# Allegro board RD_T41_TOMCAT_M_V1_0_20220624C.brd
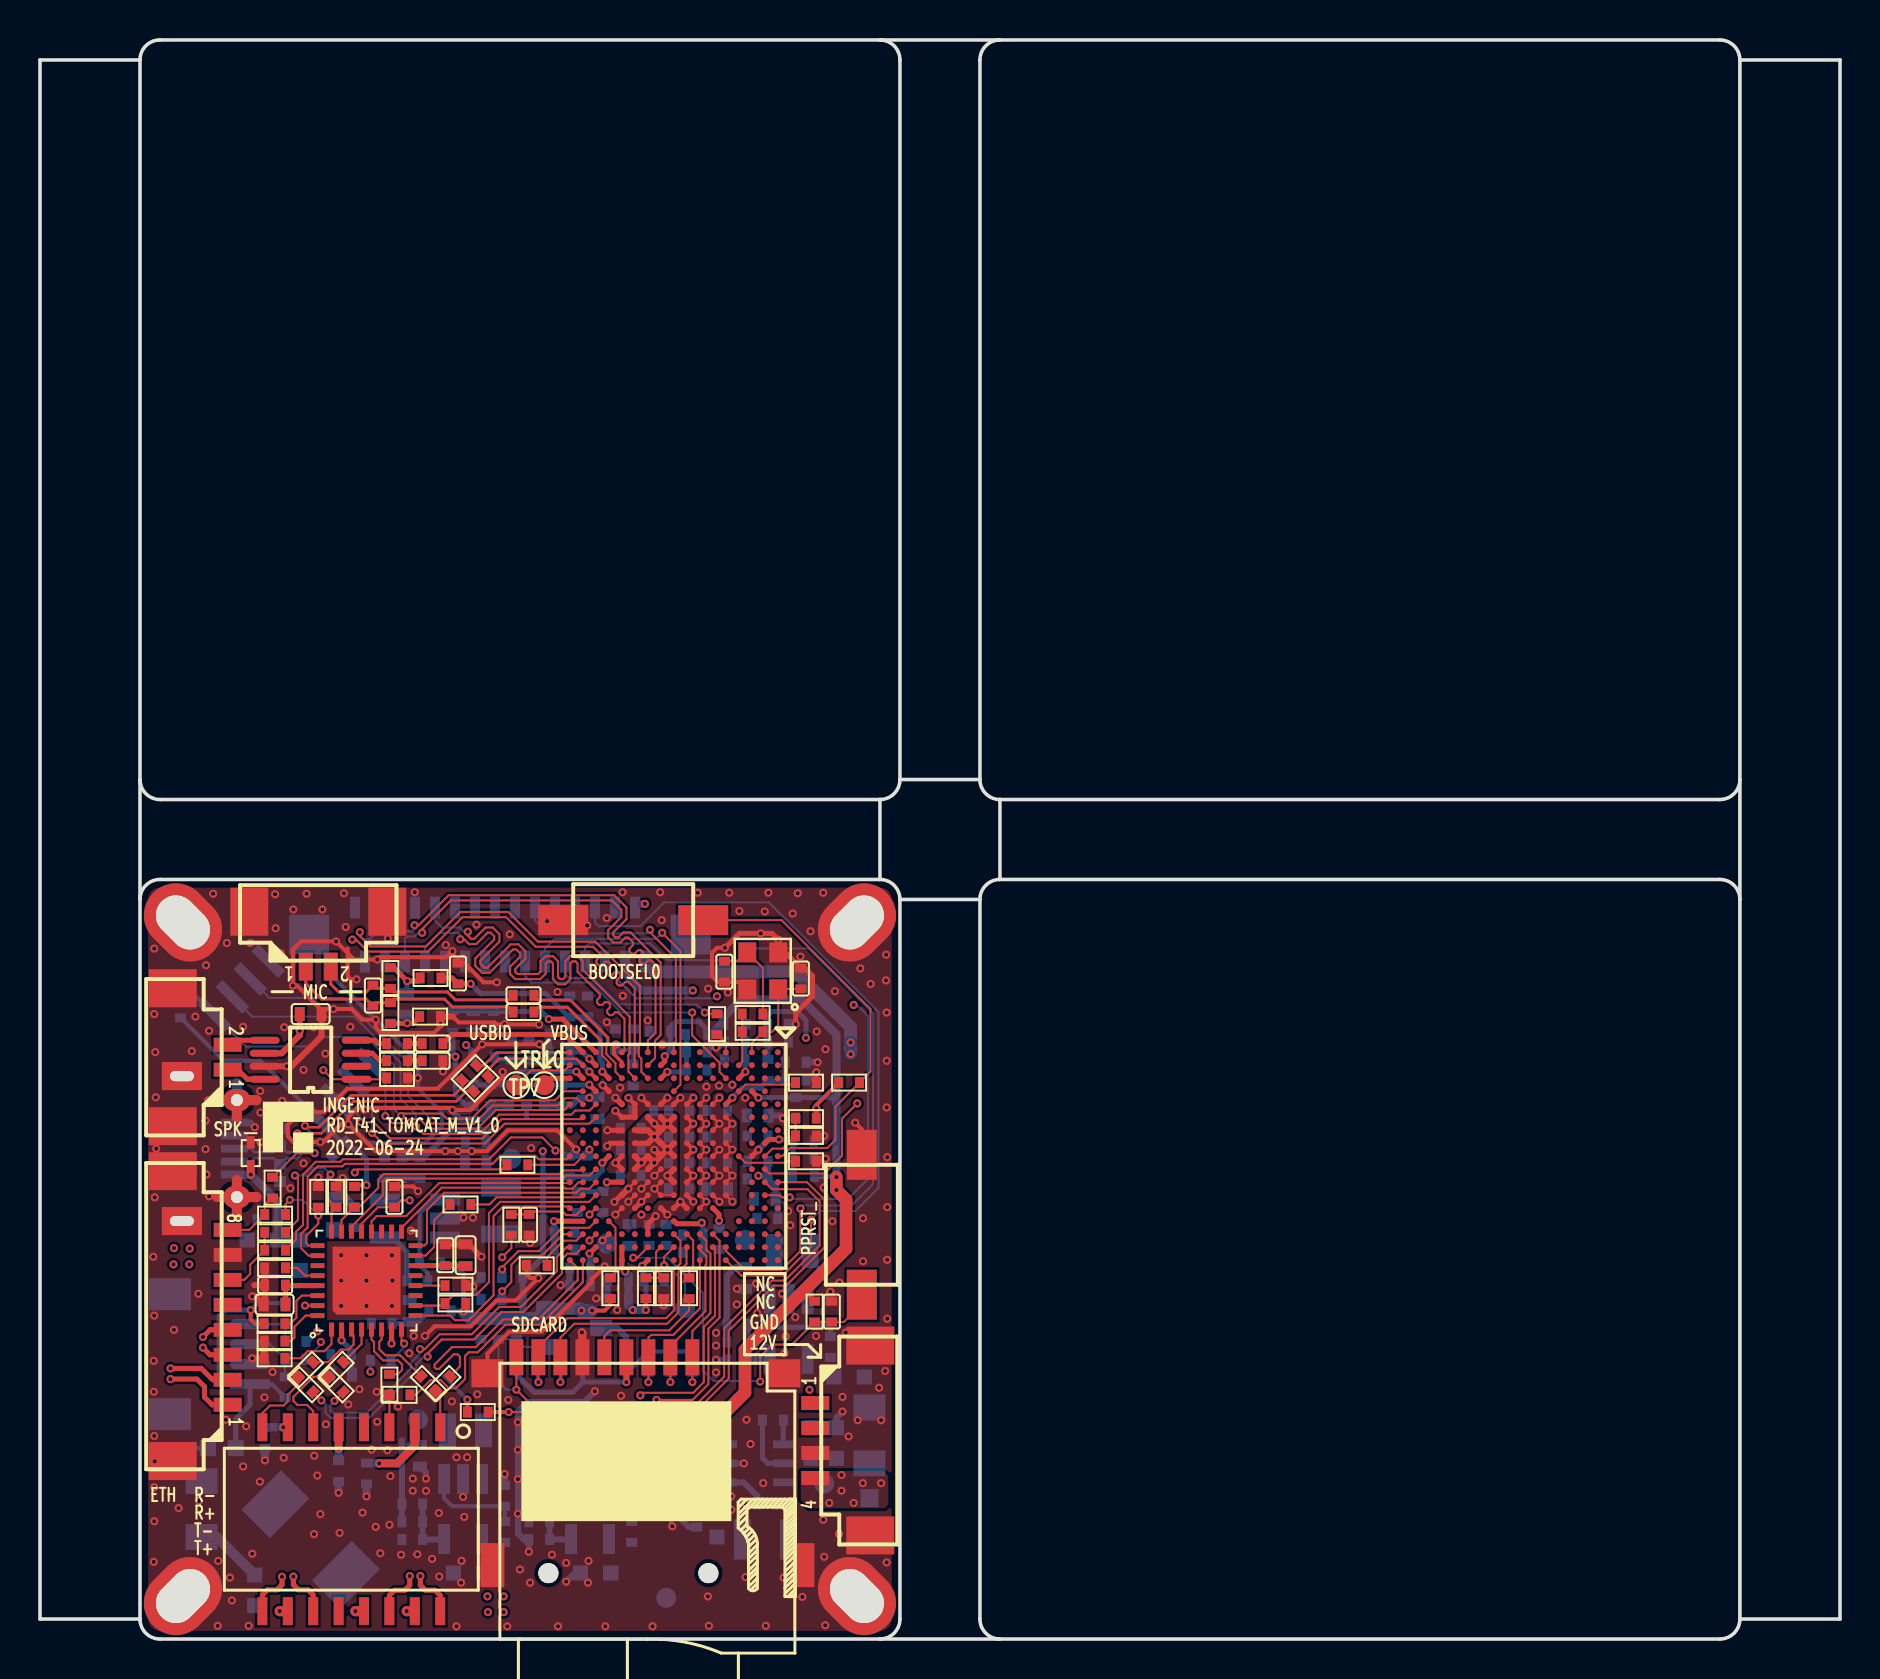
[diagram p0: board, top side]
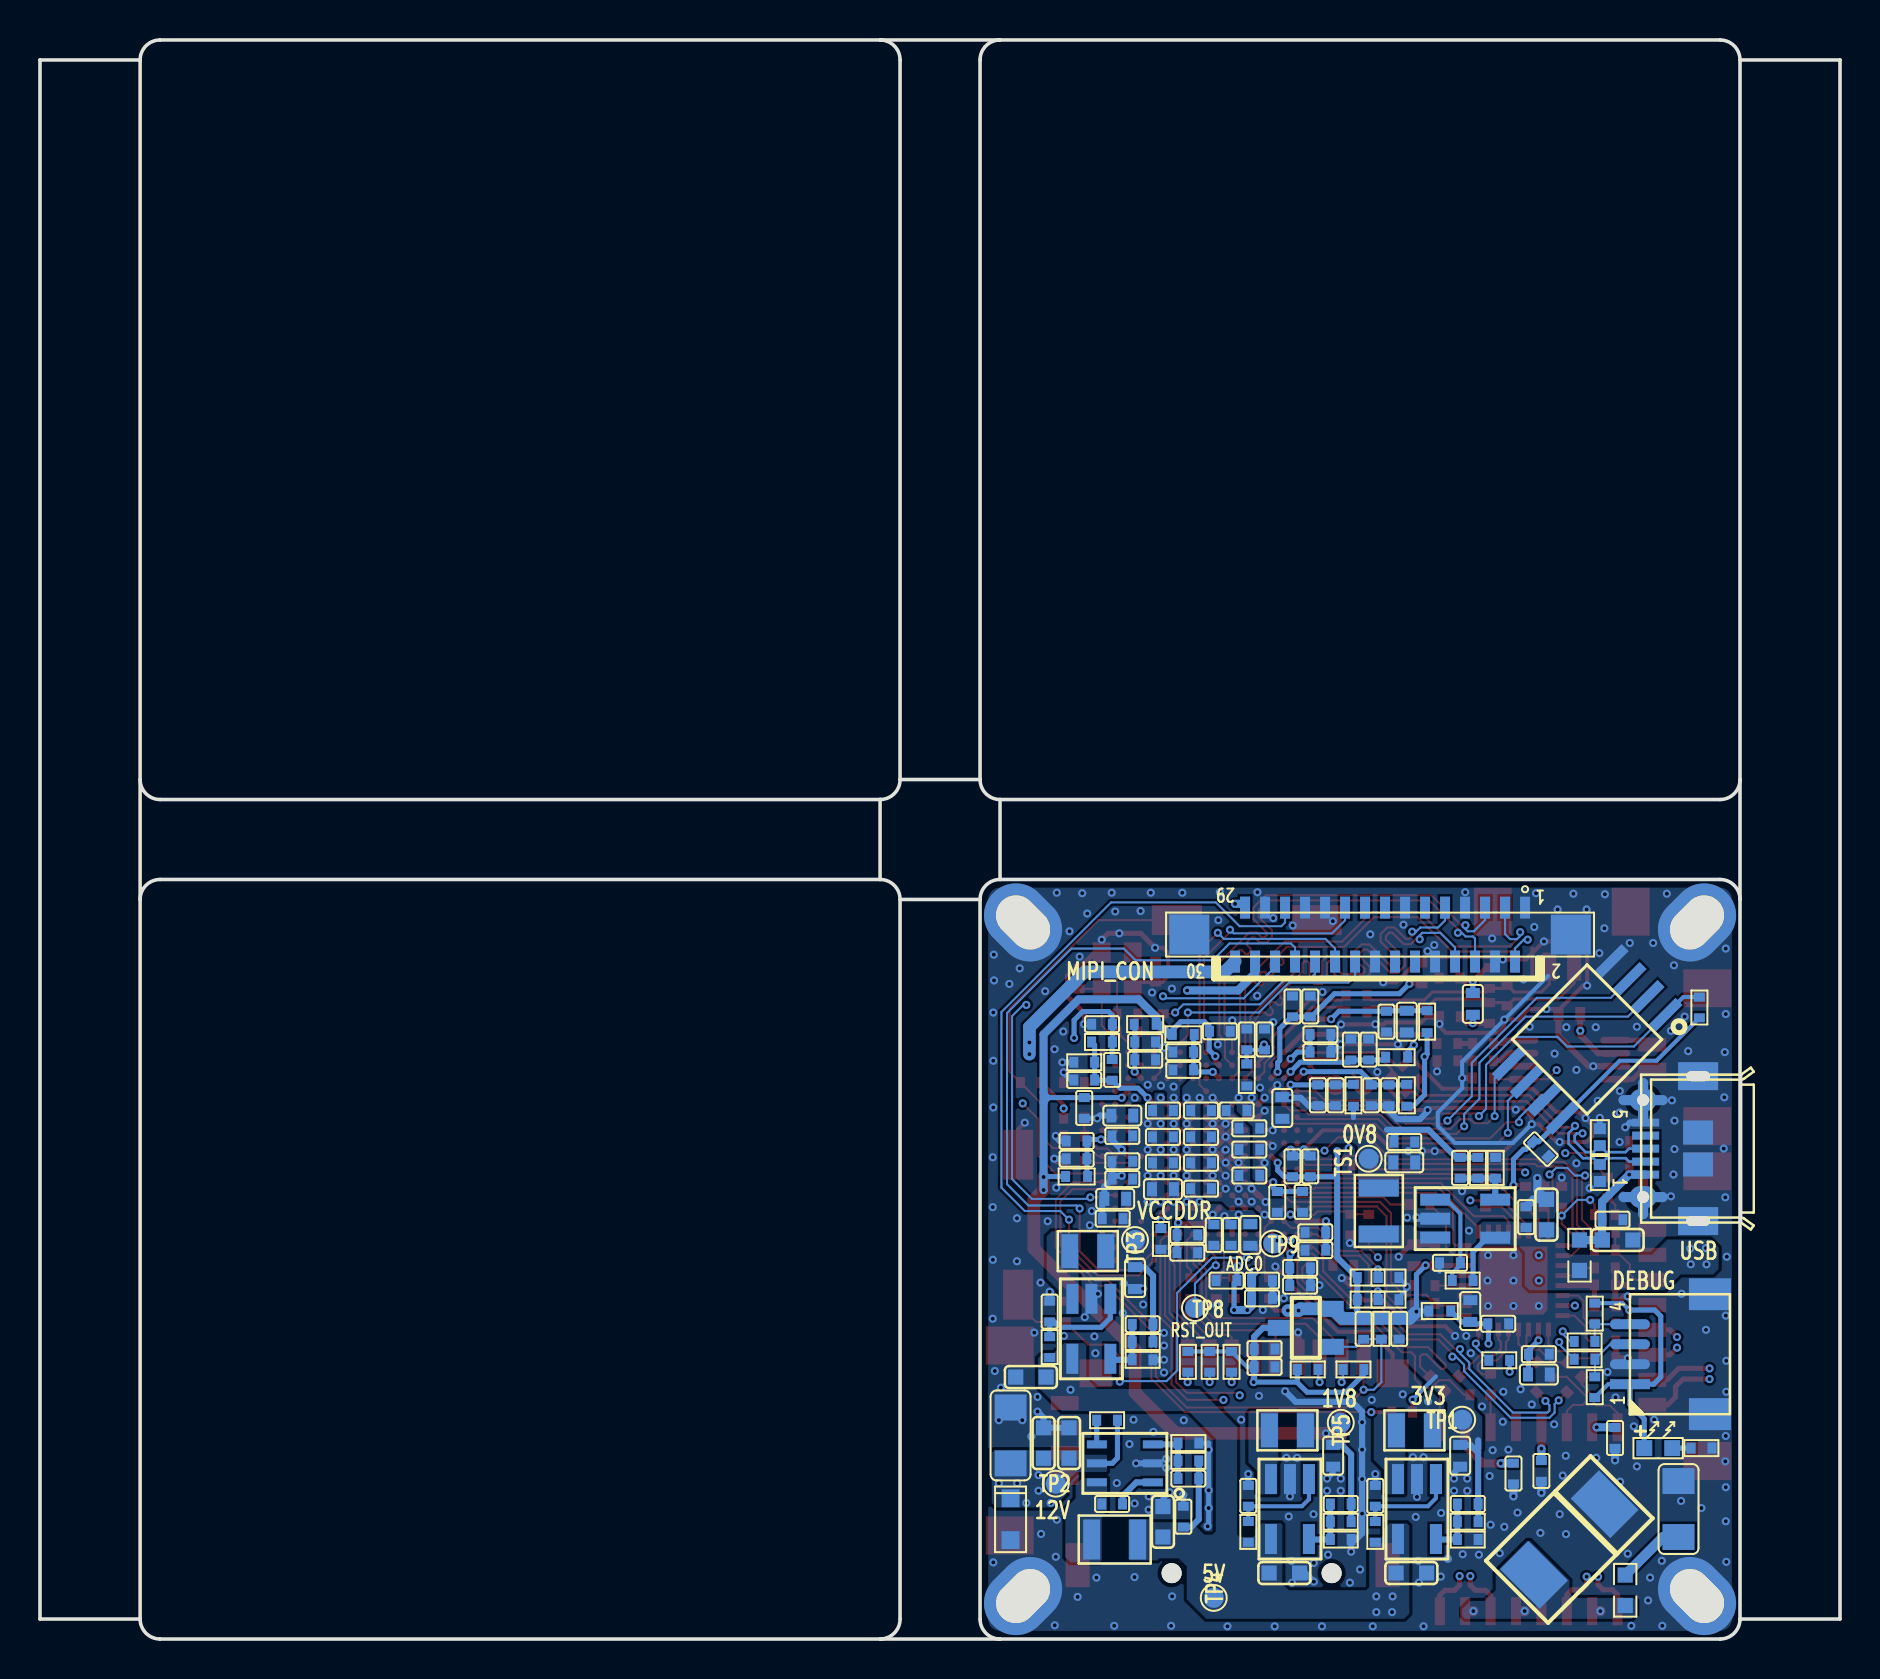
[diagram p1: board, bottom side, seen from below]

Outline 90.01 x 80 mm; copper layers: TOP, L2_GND, L3_PWR, BOTTOM. Coordinates in mm from the lower left corner of the outline.
Outline path: 5,1 0,1 0,79 5,79 ; 5,1 5,37 ; 5,1 arc(5.29,0.29) 6,0 42,0 ; 5,79 5,43 ; 5,79 arc(5.29,79.71) 6,80 42,80 ; 5,43 5,37 ; 5,43 arc(5.29,42.29) 6,42 42,42 ; 5,37 arc(5.29,37.71) 6,38 42,38 ; 42,42 42,38 ; 42,42 arc(42.71,42.29) 43,43 ; 42,38 arc(42.71,37.71) 43,37 ; 42,80 arc(42.71,79.71) 43,79 43,43 ; 42,80 48,80 ; 43,37 43,1 arc(42.71,0.29) 42,0 ; 43,37 47,37 ; 42,0 48,0 ; 48,0 arc(47.29,0.29) 47,1 47,37 ; 48,0 84,0 arc(84.71,0.29) 85,1 ; 43,43 47,43 ; 48,80 arc(47.29,79.71) 47,79 47,43 ; 48,80 84,80 arc(84.71,79.71) 85,79 ; 47,43 arc(47.29,42.29) 48,42 ; 47,37 arc(47.29,37.71) 48,38 ; 48,38 48,42 ; 48,38 84,38 arc(84.71,37.71) 85,37 ; 48,42 48.01,41.99 ; 48,42 84,42 arc(84.71,42.29) 85,43 ; 85,79 85,43 ; 85,79 90.01,79 90.01,1 85,1 ; 85,37 85,43 ; 85,37 85,1

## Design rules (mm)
net group DP_RD: nets RD_N RD_P
net group DP_TD: nets TD_N TD_P
net group DP_TRXN0: nets TRXN0 TRXP0
net group DP_TRXN1: nets TRXN1 TRXP1
net group MDI_R: nets MDI_RN MDI_RP
net group MDI_T: nets MDI_TN MDI_TP
net group MICNL: nets MICNL N16707590
net group MICPL: nets MICPL N16712105
net group RJ45_RX: nets RX+ RX-
net group RJ45_TX: nets TX+ TX-
net group USB0PN: nets N16707578 USB0PN
net group USB0PP: nets N16707574 USB0PP
net group POW: nets AVDD33 CSI_VCC08 CSI_VCC18 DDR_VREF DVDD1V2OUT MICBIAS USB_AVD08 USB_AVD18 USB_AVD33 VDDMSC0
nets with their own width: min track width 0.203; nets GND VCC_3V3

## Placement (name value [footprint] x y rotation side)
C1  22uF/25V-1206  [C1206]  41.47 10.19 90 bottom
C2  10uF/10V-0603  [C0603]  21.43 3.3 180 bottom
C3  100nF/10V  [C0402]  23.24 7.16 90 bottom
C4  22pF/50V  [C0402]  18.61 6.76 0 bottom
C5  10uF/6.3V  [C0402_E]  19 9.17 270 bottom
C6  10nF/25V  [C0402]  36.39 6.76 0 bottom
C7  10uF/25V-0603  [C0603]  39.82 9.8 90 bottom
C8  10uF/25V-0603  [C0603]  38.55 9.8 90 bottom
C9  22pF/50V  [C0402]  34.87 15.75 0 bottom
C10  22pF/50V  [C0402]  32.58 8.03 0 bottom
C11  10uF/10V-0603  [C0603]  33.85 5.87 90 bottom
C12  100nF/10V  [C0402]  32.84 6.12 90 bottom
C13  10uF/10V-0603  [C0603]  40.46 13.11 0 bottom
C14  100nF/10V  [C0402]  39.52 16.38 90 bottom
C15  10uF/6.3V  [C0402_E]  35.25 18.06 270 bottom
C16  22pF/50V  [C0402]  24.96 6.76 0 bottom
C17  10uF/6.3V  [C0402_E]  25.35 9.17 270 bottom
C18  10uF/10V-0603  [C0603]  27.78 3.3 180 bottom
C19  10uF/10V-0603  [C0603]  14.68 21.23 90 bottom
C20  100nF/10V  [C0402]  15.69 21.11 90 bottom
C21  10uF/6.3V  [C0402_E]  21.79 23.85 180 bottom
C22  100nF/6.3V  [C0402]  21.79 24.87 180 bottom
C23  22pF/50V  [C0402]  19 23.57 90 bottom
C24  100nF/6.3V  [C0402]  35.89 23.01 0 bottom
C25  10uF/6.3V  [C0402_E]  36.24 22.02 0 bottom
C26  100nF/6.3V  [C0402]  35.89 23.9 0 bottom
C27  100nF/6.3V  [C0402]  35.89 25.17 0 bottom
C28  10uF/6.3V  [C0402_E]  35.89 26.19 0 bottom
C29  1uF/6.3V  [C0402]  32.84 28.47 0 bottom
C30  1uF/6.3V  [C0402]  34.74 29.87 180 bottom
C31  1uF/6.3V  [C0402]  26.87 21.87 270 bottom
C32  10uF/6.3V  [C0402_E]  33.85 22.5 180 bottom
C33  100nF/6.3V  [C0402]  36.37 21.03 0 bottom
C34  10nF/6.3V  [C0402]  33.85 23.83 180 bottom
C35  100nF/6.3V  [C0402]  33.85 25.12 180 bottom
C36  1uF/6.3V  [C0402]  22.55 27.2 270 bottom
C37  100nF/6.3V  [C0402]  33.85 26.44 180 bottom
C38  1uF/6.3V  [C0402]  28.9 17.04 180 bottom
C39  1uF/6.3V  [C0402]  27.38 23.65 90 bottom
C40  100nF/6.3V  [C0402]  36.39 28.47 90 bottom
C41  4.7uF/6.3V  [C0402]  36.9 30.76 0 bottom
C42  100nF/6.3V  [C0402]  37.79 27.97 180 bottom
C43  10uF/6.3V  [C0402_E]  27.89 26.57 90 bottom
C44  10uF/6.3V  [C0402_E]  29.49 20.22 270 bottom
C45  100nF/6.3V  [C0402]  29.54 24.49 0 bottom
C46  100nF/6.3V  [C0402]  29.54 25.55 0 bottom
C47  100nF/6.3V  [C0402]  30.17 26.44 0 bottom
C48  100nF/6.3V  [C0402]  31.95 26.44 180 bottom
C49  100nF/6.3V  [C0402]  31.95 23.83 180 bottom
C50  100nF/6.3V  [C0402]  31.95 22.53 180 bottom
C51  1uF/6.3V  [C0402]  32.64 20.22 180 bottom
C52  10nF/6.3V  [C0402]  31.95 25.12 180 bottom
C53  10nF/6.3V  [C0402]  31.31 20.22 270 bottom
C54  1uF/6.3V  [C0402]  38.17 24.03 0 bottom
C55  10nF/6.3V  [C0402]  29.54 23.19 0 bottom
C56  10uF/6.3V  [C0402_E]  18.36 31.78 90 bottom
C57  1uF/6.3V  [C0402]  26.23 19.46 0 bottom
C58  100nF/6.3V  [C0402]  26.23 20.35 0 bottom
C59  1uF/6.3V  [C0402]  27 18.57 180 bottom
C60  100nF/6.3V  [C0402]  27 17.68 180 bottom
C61  100nF/6.3V  [C0402]  24.46 20.73 90 top
C62  100nF/10V  [C0402]  29.59 7.16 90 bottom
C63  100nF/6.3V  [C0402]  34.74 28.98 180 bottom
C64  100nF/6.3V  [C0402]  38.17 24.92 0 bottom
C65  100nF/6.3V  [C0402]  22.68 30.89 270 bottom
C66  10uF/6.3V  [C0402_E]  21.66 30.89 270 bottom
C67  100nF/6.3V  [C0402]  24.18 32.21 180 top
C68  100nF/6.3V  [C0402]  24.18 31.37 180 top
C69  4.7uF/6.3V  [C0402]  25.98 30.25 180 bottom
C70  100nF/6.3V  [C0402]  25.98 29.36 180 bottom
C71  1uF/6.3V  [C0402]  25.22 27.2 270 bottom
C72  100nF/6.3V  [C0402]  26.11 27.2 270 bottom
C73  100nF/6.3V  [C0402]  23.44 27.2 270 bottom
C74  1uF/6.3V  [C0402]  23.57 29.49 90 bottom
C75  100nF/6.3V  [C0402]  24.46 29.49 90 bottom
C76  100nF/6.3V  [C0402]  28.9 17.93 180 bottom
C78  4.7uF/6.3V  [C0402]  26.49 31.65 90 bottom
C79  100nF/6.3V  [C0402]  27.38 31.65 90 bottom
C80  12pF/50V  [C0402]  38.05 33.05 270 top
C81  100nF/6.3V  [C0402]  14.96 24.51 45 bottom
C82  12pF/50V  [C0402]  34.22 33.39 90 top
C83  100nF/6.3V  [C0402]  30.68 17.93 0 bottom
C84  1uF/6.3V  [C0402]  29.66 30 90 bottom
C85  100nF/6.3V  [C0402]  28.77 30 90 bottom
C86  100nF/6.3V  [C0402]  32.84 29.36 0 bottom
C87  100nF/6.3V  [C0402]  31.01 30.4 180 bottom
C88  100nF/6.3V  [C0402]  37.79 26.57 270 bottom
C89  100nF/6.3V  [C0402]  26.49 23.65 90 bottom
C90  100nF/6.3V  [C0402]  32.64 19.33 180 bottom
C91  4.7uF/6.3V  [C0402]  22.04 15.52 270 bottom
C92  100nF/6.3V  [C0402]  23.82 15.52 270 bottom
C93  4.7uF/6.3V  [C0402]  28.77 14.5 180 bottom
C94  100nF/6.3V  [C0402]  28.77 13.61 180 bottom
C95  10uF/10V-0603  [C0603]  11.12 19.96 180 bottom
C96  100nF/25V  [C0402]  16.33 8.28 90 bottom
C97  100nF/25V  [C0402]  14.93 8.41 90 bottom
C98  100nF/25V  [C0402]  11.25 10.06 90 bottom
C99  10uF/6.3V  [C0402_E]  21.28 19.2 90 top
C100  100nF/6.3V  [C0402]  20.27 19.2 90 top
C101  10uF/6.3V  [C0402_E]  15.06 13.23 180 bottom
C102  100nF/6.3V  [C0402]  15.06 14.25 180 bottom
C103  10uF/6.3V  [C0402_E]  11.73 16.74 180 top
C104  100nF/6.3V  [C0402]  11.76 17.7 180 top
C105  100pF/50V  [C0402]  16.65 32.19 90 top
C106  3.3nF/50V  [C0402]  19.63 28.93 0 top
C107  3.3nF/50V  [C0402]  19.63 29.79 0 top
C108  10uF/6.3V  [C0402_E]  13.53 31.27 0 top
C110  4.7uF/6.3V  [C0402]  20.9 33.3 90 top
C111  1uF/6.3V  [C0402]  39.59 16.38 90 top
C112  100nF/10V  [C0402]  19.5 18.82 0 bottom
C113  100nF/6.3V  [C0402]  30.45 20.22 270 bottom
C114  100nF/6.3V  [C0402]  28.14 21.87 270 bottom
C119  100nF/10V  [C0402]  11.38 20.98 180 bottom
C125  100nF/6.3V  [C0402]  17.73 22.12 90 top
C126  1nF/2KV-1206  [C1206]  8.07 6.5 270 bottom
C127  10uF/6.3V  [C0402_E]  18.49 16.41 90 bottom
C128  100nF/6.3V  [C0402]  17.09 15.77 180 bottom
D1  BZT52C12S  [SOD323]  41.47 5.99 90 bottom
D2  LED Red  [D0603_LED]  9.09 9.55 180 bottom
D3  LXES1UTAA1-157  [DFN1006]  12.01 25.11 90 bottom
D4  P3100SC  [SMB]  13.53 4.98 315 bottom
D5  LXES1UTAA1-157  [DFN1006]  12.01 23.32 270 bottom
D6  ESD5451X  [ESD0402]  10.54 24.31 270 top
FB1  1000ohm/250mA  [FB0402]  38.17 23.14 0 bottom
FB2  1000ohm/250mA  [FB0402]  20.01 16.41 0 bottom
FB3  1000ohm/250mA  [FB0402]  34.74 30.76 180 bottom
FB4  1000ohm/250mA  [FB0402]  24.33 27.2 90 bottom
FB5  1000ohm/250mA  [FB0402]  21.66 27.2 90 bottom
FB6  1000ohm/250mA  [FB0402]  22.17 29.11 0 bottom
FB7  1000ohm/250mA  [FB0402]  20.65 30.89 90 bottom
FB8  1000ohm/250mA  [FB0402]  29.66 28.22 270 bottom
FB9  1000ohm/250mA  [FB0402]  32.84 30.25 0 bottom
H1  MHOBL  [MHOLE_3D0X2D0]  7.15 35.85 90 top
H2  MHOBL  [MHOLE_3D0X2D0]  40.85 2.15 90 top
H3  MHOBL  [MHOLE_3D0X2D0]  7.15 2.15 0 top
H4  MHOBL  [MHOLE_3D0X2D0]  40.85 35.85 0 top
J1  CON4 1.25mm LT  [CON4-1D25-LT]  40.97 9.93 90 top
J2  MICROSD_TF  [TFCARD]  30.37 13.9 0 top
J3  CON30 0.5mm LT  [FPC-CON30-0D5-LT]  23 35.24 0 bottom
J4  MICRO USB  [MICROUSB_B_NJ5P]  9.72 24.54 270 bottom
J5  CON8 1.25mm LT  [CON8-1D25-LT]  7.18 16.15 270 top
J6  CON2 1.25mm LT  [CON2-1D25-LT]  13.92 35.84 180 top
J7  CON2 1.25mm LT  [CON2-1D25-LT]  7.18 29.11 270 top
J8  CON4 1.0mm WT  [CON4-1D0-WT]  8 14.25 90 bottom
L1  2.2uH/1.3A-2016  [L2016]  21.28 10.44 0 bottom
L2  4.7uH/1.4A-2520  [L2520]  36.27 4.98 180 bottom
L3  2.2uH/1.3A-2016  [L2016]  37.61 19.41 0 bottom
L4  2.2uH/2.2A-2520  [L2520]  23.06 21.41 90 bottom
L5  2.2uH/1.3A-2016  [L2016]  27.63 10.44 0 bottom
NOREF  -  []  5.32 37.73 0 top
NOREF#2  -  []  12.87 25.59 0 top
NOREF#3  -  []  -41.62 136.12 0 top
NOREF#4  -  []  6 0 90 top
NOREF#5  -  []  41.27 158.18 0 top
NOREF#6  -  []  -189.11 -122.58 0 top
NOREF#7  -  []  5 1 0 top
Q1  WPM3401  [SOT23]  26.71 15.57 90 bottom
R1  100K  [R0402]  23.24 5.36 90 bottom
R2  150K/1%  [R0402]  18.61 5.87 180 bottom
R3  33.2K/1%  [R0402]  18.61 4.98 0 bottom
R4  100K  [R0402]  36.65 10.95 0 bottom
R5  100K  [R0402]  39.52 14.61 90 bottom
R6  200K/1%  [R0402]  32.58 8.92 0 bottom
R7  150K/1%  [R0402]  34.87 14.86 180 bottom
R8  27K/1%  [R0402]  32.58 9.8 0 bottom
R9  100K/1%  [R0402]  34.87 13.97 0 bottom
R10  100K  [R0402]  18.87 17.93 0 bottom
R11  100K  [R0402]  29.59 5.36 90 bottom
R13  2.2R/1%  [R0402]  13.28 12.73 135 top
R14  1K  [R0402]  6.93 9.55 180 bottom
R15  100K/1%  [R0402]  36.9 29.87 180 bottom
R16  240R/1%  [R0402]  33.96 20.02 270 bottom
R17  100K/1%  [R0402]  37.79 28.85 180 bottom
R18  240R/1%  [R0402]  38.3 23.9 0 top
R19  33R  [R0402]  21.03 21.74 180 top
R20  1K  [R0402]  30.3 17.55 90 top
R21  33R  [R0402]  38.3 27.84 180 top
R22  10K  [R0402]  7.03 31.6 270 bottom
R23  1M  [R0402]  35.63 30.38 0 top
R24  33R  [R0402]  35.63 31.27 180 top
R25  33R  [R0402]  32.46 17.55 90 top
R26  2.49K/1%  [R0402]  24.84 18.69 180 top
R27  1K  [R0402]  22.58 16.98 0 bottom
R28  2.2R/1%  [R0402]  14.8 12.73 135 top
R29  100K  [R0402]  26.62 13.49 180 bottom
R30  100K  [R0402]  30.43 13.87 270 bottom
R31  100K  [R0402]  24.33 13.49 0 bottom
R32  100K  [R0402]  32.61 13.87 270 bottom
R33  100K  [R0402]  31.52 13.87 270 bottom
R34  100K  [R0402]  22.93 15.52 270 bottom
R35  2.2R/1%  [R0402]  13.28 13.49 225 top
R36  2.2R/1%  [R0402]  14.8 13.49 225 top
R37  10K  [R0402]  15.72 22.12 270 top
R39  2.2R/1%  [R0402]  17.47 12.73 270 top
R40  2.2R/1%  [R0402]  19.42 12.78 315 top
R41  2.49K/1%  [R0402]  11.73 14.05 180 top
R44  10K  [R0402]  20.77 16.79 180 top
R46  10K  [R0402]  11.76 18.57 0 top
R47  0R  [R0402]  11.73 14.91 0 top
R48  1.1K  [R0402]  17.52 31.32 270 top
R49  1.1K  [R0402]  19.5 31.14 180 top
R50  10K  [R0402]  17.85 28.07 0 top
R51  1.1K  [R0402]  17.52 33.07 270 top
R52  68K/1%  [R0402]  17.85 28.93 0 top
R53  68K/1%  [R0402]  17.85 29.79 0 top
R55  100K  [R0402]  40.46 27.84 180 top
R56  100K  [R0402]  38.3 26.06 0 top
R57  10K  [R0402]  12.26 12.6 90 bottom
R58  10K  [R0402]  12.26 16.28 270 bottom
R59  100K  [R0402]  38.3 25.17 180 top
R60  33R  [R0402]  12.77 14.88 0 bottom
R61  33R  [R0402]  12.77 14 0 bottom
R62  100K  [R0402]  38.73 16.38 270 top
R63  100K/1%  [R0402]  18.11 23.57 90 bottom
R64  300K/1%  [R0402]  17.22 23.57 90 bottom
R65  10K  [R0402]  23.62 18.08 0 bottom
R66  33R  [R0402]  23.87 23.72 0 top
R67  33R  [R0402]  33.85 30.76 270 top
R68  10K  [R0402]  28.52 17.55 270 top
R69  10K  [R0402]  23.62 16.98 0 bottom
R70  10K  [R0402]  21.89 11.35 180 top
R71  1K  [R0402]  22.58 18.08 0 bottom
R72  2.2R/1%  [R0402]  17.98 12.22 180 top
R73  2.2R/1%  [R0402]  20.14 12.78 225 top
R74  330R  [R0402]  11.76 19.46 180 top
R75  330R  [R0402]  11.63 22.58 270 top
R76  330R  [R0402]  11.76 21.23 0 top
R77  330R  [R0402]  11.76 20.35 0 top
R78  1K  [R0402]  31.19 17.55 90 top
R81  1.1K  [R0402]  19.53 33.07 180 top
R85  0R-0603  [R0603]  13.03 19.2 270 bottom
R86  200K/1%  [R0402]  24.96 5.87 180 bottom
R87  10K  [R0402]  17.04 13.94 0 bottom
R88  10K  [R0402]  14.8 22.12 270 top
R89  10K  [R0402]  13.92 22.12 270 top
R92  10K  [R0402]  20.77 17.68 180 top
R93  75R/1%-0603  [R0603]  10.74 2.44 270 bottom
R94  10K  [R0402]  11.73 15.77 180 top
R98  100K/1%  [R0402]  24.96 4.98 0 bottom
R99  0R  [R0402]  23.57 20.73 270 top
R100  2.2R/5%  [R0402]  21.47 28.33 225 top
R101  2.2R/5%  [R0402]  22.05 27.77 225 top
SW1  KEY2_SMD  [SW2_SMD]  29.66 35.97 0 top
SW2  KEY2_SMD  [SW2_SMD]  41.09 20.73 270 top
TP1  1mm_SMD  [TEST_SMD]  18.89 10.97 180 bottom
TP2  1mm_SMD  [TEST_SMD]  39.21 7.77 180 bottom
TP3  1mm_SMD  [TEST_SMD]  35.25 19.96 90 bottom
TP4  1mm_SMD  [TEST_SMD]  31.31 2.06 90 bottom
TP5  1mm_SMD  [TEST_SMD]  24.96 10.82 90 bottom
TP7  1mm_SMD  [TEST_SMD]  23.82 27.71 0 top
TP8  1mm_SMD  [TEST_SMD]  32.25 16.56 180 bottom
TP9  1mm_SMD  [TEST_SMD]  28.34 19.79 180 bottom
TP10  1mm_SMD  [TEST_SMD]  25.22 27.71 0 top
TS1  1mm_SMD  [TEST_SMD]  23.57 24.03 90 bottom
U1  LN5058  [SOT23-5]  21.15 6.5 0 bottom
U2  ETA8120  [SOT23-6]  35.76 8.79 0 bottom
U3  LN5058  [SOT23-5]  37.44 15.52 0 bottom
U4  LN5058  [SOT23-5]  27.5 6.5 0 bottom
U5  ETA3409  [SOT23-5]  18.74 21.03 270 bottom
U6  T41 BGA232  [BGA232_0D65_T41]  31.7 24.16 270 top
U7  GD25Q127CSIG  [WSOP8_1D27]  12.65 30 315 bottom
U8  SZ18201  [QFN32_0D5_SZ18201]  16.33 17.93 90 top
U9  FC1680C  [QFP16_1D27]  15.57 5.99 270 top
U10  CS8302M  [MSOP8_0D65]  13.53 28.98 90 top
Y1  24M 2016  [CRY_2D5X2D0]  36.14 33.43 90 top

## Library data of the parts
C1-C66 C69-C76 C78-C108 C110-C114 C119 C125-C128 = CAP
C67 C68 = CAP: signal model: CAP_C0402_100NF/6.3V_100nF/6.3V
D1 = DIODE_WY
D2 = LED_1
D3 D5 D6 = ESD
D4 = P3100
FB1-FB9 = BEAD
H1-H4 = MHOLE1
J1 = CON_4x1
J2 = MMC_SD
J3 = FPCCON_15x2
J4 = MICROUSB_0
J5 = CON_8x1
J6 J7 = CON_2X1
J8 = CON_4X1
L1-L5 = INDUCTOR
Q1 = P_MOS
R1-R11 R13-R37 R39-R41 R44 R46-R53 R55-R78 R81 R85-R89 R92-R94 R98 R99 = RES
R100 R101 = RES: signal model: RES_R0402_2.2R/5%_2.2R/5%
SW1 SW2 = PUSHBUTTON
TP1-TP5 TP7-TP10 TS1 = TP
U1 U3-U5 = SY8088
U2 = SY8120
U6 = T41_BGA232
U7 = SPI_NOR
U8 = SZ18201
U9 = FC1680C
U10 = CS8302
Y1 = XTAL_P4

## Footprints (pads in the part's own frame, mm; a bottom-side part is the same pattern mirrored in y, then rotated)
BGA232_0D65_T41
  round 0.3 smd: A1(-5.2,5.2) A2(-4.55,5.2) A3(-3.9,5.2) A5(-2.6,5.2) A7(-1.3,5.2) A9(0,5.2) A11(1.3,5.2) A13(2.6,5.2) A15(3.9,5.2) A16(4.55,5.2) A17(5.2,5.2) B1(-5.2,4.55) B2(-4.55,4.55) B3(-3.9,4.55) B4(-3.25,4.55) B5(-2.6,4.55) B6(-1.95,4.55) B7(-1.3,4.55) B8(-0.65,4.55) B9(0,4.55) B10(0.65,4.55) B11(1.3,4.55) B12(1.95,4.55) B13(2.6,4.55) B14(3.25,4.55) B15(3.9,4.55) B16(4.55,4.55) B17(5.2,4.55) C1(-5.2,3.9) C2(-4.55,3.9) C3(-3.9,3.9) C4(-3.25,3.9) C5(-2.6,3.9) C6(-1.95,3.9) C7(-1.3,3.9) C8(-0.65,3.9) C9(0,3.9) C10(0.65,3.9) C11(1.3,3.9) C12(1.95,3.9) C13(2.6,3.9) C14(3.25,3.9) C15(3.9,3.9) C16(4.55,3.9) C17(5.2,3.9) D2(-4.55,3.25) D3(-3.9,3.25) D4(-3.25,3.25) D9(0,3.25) D14(3.25,3.25) D15(3.9,3.25) D16(4.55,3.25) E1(-5.2,2.6) E2(-4.55,2.6) E3(-3.9,2.6) E5(-2.6,2.6) E6(-1.95,2.6) E7(-1.3,2.6) E8(-0.65,2.6) E9(0,2.6) E10(0.65,2.6) E11(1.3,2.6) E12(1.95,2.6) E15(3.9,2.6) E16(4.55,2.6) E17(5.2,2.6) F2(-4.55,1.95) F3(-3.9,1.95) F5(-2.6,1.95) F6(-1.95,1.95) F7(-1.3,1.95) F8(-0.65,1.95) F9(0,1.95) F10(0.65,1.95) F11(1.3,1.95) F12(1.95,1.95) F13(2.6,1.95) F15(3.9,1.95) F16(4.55,1.95) G1(-5.2,1.3) G2(-4.55,1.3) G3(-3.9,1.3) G5(-2.6,1.3) G6(-1.95,1.3) G7(-1.3,1.3) G8(-0.65,1.3) G9(0,1.3) G10(0.65,1.3) G11(1.3,1.3) G12(1.95,1.3) G13(2.6,1.3) G15(3.9,1.3) G16(4.55,1.3) G17(5.2,1.3) H2(-4.55,0.65) H3(-3.9,0.65) H5(-2.6,0.65) H6(-1.95,0.65) H7(-1.3,0.65) H8(-0.65,0.65) H9(0,0.65) H10(0.65,0.65) H11(1.3,0.65) H12(1.95,0.65) H13(2.6,0.65) H15(3.9,0.65) H16(4.55,0.65) J1(-5.2,0) J2(-4.55,0) J3(-3.9,0) J4(-3.25,0) J5(-2.6,0) J6(-1.95,0) J7(-1.3,0) J8(-0.65,0) J9(0,0) J10(0.65,0) J11(1.3,0) J12(1.95,0) J13(2.6,0) J14(3.25,0) J15(3.9,0) J16(4.55,0) J17(5.2,0) K2(-4.55,-0.65) K3(-3.9,-0.65) K5(-2.6,-0.65) K6(-1.95,-0.65) K7(-1.3,-0.65) K8(-0.65,-0.65) K9(0,-0.65) K10(0.65,-0.65) K11(1.3,-0.65) K12(1.95,-0.65) K13(2.6,-0.65) K15(3.9,-0.65) K16(4.55,-0.65) L1(-5.2,-1.3) L2(-4.55,-1.3) L3(-3.9,-1.3) L5(-2.6,-1.3) L6(-1.95,-1.3) L7(-1.3,-1.3) L8(-0.65,-1.3) L9(0,-1.3) L10(0.65,-1.3) L11(1.3,-1.3) L12(1.95,-1.3) L13(2.6,-1.3) L15(3.9,-1.3) L16(4.55,-1.3) L17(5.2,-1.3) M2(-4.55,-1.95) M3(-3.9,-1.95) M5(-2.6,-1.95) M6(-1.95,-1.95) M7(-1.3,-1.95) M8(-0.65,-1.95) M9(0,-1.95) M10(0.65,-1.95) M11(1.3,-1.95) M12(1.95,-1.95) M13(2.6,-1.95) M15(3.9,-1.95) M16(4.55,-1.95) N1(-5.2,-2.6) N2(-4.55,-2.6) N3(-3.9,-2.6) N5(-2.6,-2.6) N6(-1.95,-2.6) N7(-1.3,-2.6) N8(-0.65,-2.6) N9(0,-2.6) N10(0.65,-2.6) N11(1.3,-2.6) N12(1.95,-2.6) N13(2.6,-2.6) N15(3.9,-2.6) N16(4.55,-2.6) N17(5.2,-2.6) P2(-4.55,-3.25) P3(-3.9,-3.25) P4(-3.25,-3.25) P9(0,-3.25) P14(3.25,-3.25) P15(3.9,-3.25) P16(4.55,-3.25) R1(-5.2,-3.9) R2(-4.55,-3.9) R3(-3.9,-3.9) R4(-3.25,-3.9) R5(-2.6,-3.9) R6(-1.95,-3.9) R7(-1.3,-3.9) R8(-0.65,-3.9) R9(0,-3.9) R10(0.65,-3.9) R11(1.3,-3.9) R12(1.95,-3.9) R13(2.6,-3.9) R14(3.25,-3.9) R15(3.9,-3.9) R16(4.55,-3.9) R17(5.2,-3.9) T1(-5.2,-4.55) T2(-4.55,-4.55) T3(-3.9,-4.55) T4(-3.25,-4.55) T5(-2.6,-4.55) T6(-1.95,-4.55) T7(-1.3,-4.55) T8(-0.65,-4.55) T9(0,-4.55) T10(0.65,-4.55) T11(1.3,-4.55) T12(1.95,-4.55) T13(2.6,-4.55) T14(3.25,-4.55) T15(3.9,-4.55) T16(4.55,-4.55) T17(5.2,-4.55) U1(-5.2,-5.2) U2(-4.55,-5.2) U3(-3.9,-5.2) U5(-2.6,-5.2) U7(-1.3,-5.2) U9(0,-5.2) U11(1.3,-5.2) U13(2.6,-5.2) U15(3.9,-5.2) U16(4.55,-5.2) U17(5.2,-5.2)
C0402
  rect 0.45x0.55 smd: 1(-0.52,0) 2(0.52,0)
C0402_E
  rect 0.5x0.7 smd: 1(-0.545,0) 2(0.545,0)
C0603
  rect 0.76x0.76 smd: 1(-0.762,0) 2(0.762,0)
C1206
  rect 1.3x1.6 smd: 1(-1.4,0) 2(1.4,0)
CON2-1D25-LT
  rect 0.7x1.4 smd: 1(0.625,2.2) 2(-0.625,2.2)
  rect 1.9x2.4 smd: 3(-3.45,-0.55) 4(3.45,-0.55)
CON4-1D0-WT
  rect 0.5x2 smd: 1(-1.5,2.5)
  oval 0.5x2 smd: 2(-0.5,2.5) 3(0.5,2.5) 4(1.5,2.5)
  rect 1.6x2.1 smd: 5(3,-1.5) 6(-3,-1.5)
CON4-1D25-LT
  rect 0.7x1.4 smd: 1(1.875,2.2) 2(0.625,2.2) 3(-0.625,2.2) 4(-1.875,2.2)
  rect 1.9x2.4 smd: 5(-4.75,-0.55) 6(4.75,-0.55)
CON8-1D25-LT
  rect 0.7x1.4 smd: 1(4.435,2.2) 2(3.185,2.2) 3(1.935,2.2) 4(0.685,2.2) 5(-0.565,2.2) 6(-1.815,2.2) 7(-3.065,2.2) 8(-4.315,2.2)
  rect 1.9x2.4 smd: 9(-7.25,-0.55) 10(7.25,-0.55)
CRY_2D5X2D0
  rect 1x0.9 smd: 1(-0.925,-0.775) 2(0.925,-0.775) 3(0.925,0.775) 4(-0.925,0.775)
D0603_LED
  rect 0.8x0.8 smd: 1(-0.7,0) 2(0.7,0)
DFN1006
  rect 0.55x0.6 smd: 1(0.425,0) 2(-0.425,0)
ESD0402
  rect 0.62x0.4 smd: 1(-0.54,0)
  rect 0.5x0.4 smd: 2(0.6,0)
FB0402
  rect 0.45x0.55 smd: 1(-0.55,0) 2(0.55,0)
FPC-CON30-0D5-LT
  rect 0.5x1.1 smd: 1(-7.25,-1.35) 2(-6.75,1.35) 3(-6.25,-1.35) 4(-5.75,1.35) 5(-5.25,-1.35) 6(-4.75,1.35) 7(-4.25,-1.35) 8(-3.75,1.35) 9(-3.25,-1.35) 10(-2.75,1.35) 11(-2.25,-1.35) 12(-1.75,1.35) 13(-1.25,-1.35) 14(-0.75,1.35) 15(-0.25,-1.35) 16(0.25,1.35) 17(0.75,-1.35) 18(1.25,1.35) 19(1.75,-1.35) 20(2.25,1.35) 21(2.75,-1.35) 22(3.25,1.35) 23(3.75,-1.35) 24(4.25,1.35) 25(4.75,-1.35) 26(5.25,1.35) 27(5.75,-1.35) 28(6.25,1.35) 29(6.75,-1.35) 30(7.25,1.35)
  rect 2x2 smd: 31(-9.54,0) 32(9.54,0)
L2016
  rect 0.85x1.7 smd: 1(0.9,0) 2(-0.9,0)
L2520
  rect 0.85x2 smd: 1(-1.15,0) 2(1.15,0)
MHOLE_3D0X2D0
  oval 4.2x3.2 hole 3x2 rot 45: 1(0,0)
MICROUSB_B_NJ5P
  rect 0.4x1.35 smd: 1(1.3,0) 2(0.65,0) 3(0,0) 4(-0.65,0) 5(-1.3,0)
  rect 1.4x2 hole 0.5x1.2: 6(3.625,2.625) 7(-3.625,2.625)
  oval 1.1x1.35 hole 0.6: 8(-2.425,-0.125) 9(2.425,-0.125)
  rect 1.2x1.5 smd: 10(-0.8,2.625) 11(0.8,2.625)
MSOP8_0D65
  oval 0.35x1.5 smd: 1(-0.975,-2.3) 2(-0.325,-2.3) 3(0.325,-2.3) 4(0.975,-2.3) 5(0.975,2.3) 6(0.325,2.3) 7(-0.325,2.3) 8(-0.975,2.3)
QFN32_0D5_SZ18201
  rect 0.7x0.25 smd: 1(-2.45,1.75) 2(-2.45,1.25) 3(-2.45,0.75) 4(-2.45,0.25) 5(-2.45,-0.25) 6(-2.45,-0.75) 7(-2.45,-1.25) 8(-2.45,-1.75) 17(2.45,-1.75) 18(2.45,-1.25) 19(2.45,-0.75) 20(2.45,-0.25) 21(2.45,0.25) 22(2.45,0.75) 23(2.45,1.25) 24(2.45,1.75)
  rect 0.25x0.7 smd: 9(-1.75,-2.45) 10(-1.25,-2.45) 11(-0.75,-2.45) 12(-0.25,-2.45) 13(0.25,-2.45) 14(0.75,-2.45) 15(1.25,-2.45) 16(1.75,-2.45) 25(1.75,2.45) 26(1.25,2.45) 27(0.75,2.45) 28(0.25,2.45) 29(-0.25,2.45) 30(-0.75,2.45) 31(-1.25,2.45) 32(-1.75,2.45)
  custom 0.85x0.85 smd: 33(0,0)
QFP16_1D27
  rect 1.4x0.5 smd: 1(-4.6,4.445) 2(-4.6,3.175) 3(-4.6,1.905) 4(-4.6,0.635) 5(-4.6,-0.635) 6(-4.6,-1.905) 7(-4.6,-3.175) 8(-4.6,-4.445) 9(4.6,-4.445) 10(4.6,-3.175) 11(4.6,-1.905) 12(4.6,-0.635) 13(4.6,0.635) 14(4.6,1.905) 15(4.6,3.175) 16(4.6,4.445)
R0402
  rect 0.45x0.55 smd: 1(-0.52,0) 2(0.52,0)
R0603
  rect 0.76x0.76 smd: 1(-0.762,0) 2(0.762,0)
SMB
  rect 2x2.8 smd: 1(2.5,0) 2(-2.5,0)
SOD323
  rect 0.9x0.9 smd: 1(-1.05,0) 2(1.05,0)
SOT23
  rect 0.8x1.1 smd: 1(-0.95,-1.35) 2(0.95,-1.35) 3(0,1.35)
SOT23-5
  rect 0.6x1.5 smd: 1(-0.95,-1.5) 2(0,-1.5) 3(0.95,-1.5) 4(0.95,1.5) 5(-0.95,1.5)
SOT23-6
  rect 1x0.4 smd: 1(-1.4,0.95) 2(-1.4,0) 3(-1.4,-0.95) 4(1.4,-0.95) 5(1.4,0) 6(1.4,0.95)
SW2_SMD
  rect 2.5x1.5 smd: 1(-3.5,0) 2(3.5,0)
TEST_SMD
  round 1 smd: 1(0,0)
TFCARD
  round 1 hole 1 unplated: (-4.95,-10.6) (3.05,-10.6)
  rect 0.7x1.8 smd: 1(2.25,0.2) 2(1.15,0.2) 3(0.05,0.2) 4(-1.05,0.2) 5(-2.15,0.2) 6(-3.25,0.2) 7(-4.35,0.2) 8(-5.45,0.2) 9(-6.55,0.2)
  rect 1.6x1.4 smd: 10(-8,-0.6) 13(6.85,-0.6)
  rect 1.2x2.2 smd: 11(-7.75,-10.2) 12(7.75,-10.2)
WSOP8_1D27
  rect 1.9x0.5 smd: 1(-3.645,1.905) 2(-3.645,0.635) 3(-3.645,-0.635) 4(-3.645,-1.905) 5(3.645,-1.905) 6(3.645,-0.635) 7(3.645,0.635) 8(3.645,1.905)

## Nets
AVDD33: C127.1 C128.1 FB2.1 U8.7(AVDD33_1)
AVDDL_REG: C59.1 C60.1 U6.R16(AVDDL_REG)
DVDD1V2OUT: C57.1 C58.1 U6.T14(DVDD1V2OUT)
GND: C1.2 C2.2 C3.2 C5.2 C7.2 C8.2 C11.2 C12.2 C13.2 C14.2 C15.2 C17.2 C18.2 C19.2 C20.2 C21.2 C22.2 C24.2 C25.2 C26.2 C27.2 C28.2 C29.2 C30.2 C31.2 C32.2 C33.2 C34.2 C35.2 C36.2 C37.2 C38.2 C39.2 C41.2 C42.1 C43.2 C44.2 C45.2 C46.2 C47.2 C48.2 C49.2 C50.2 C51.2 C52.2 C53.2 C54.2 C55.2 C57.2 C58.2 C59.2 C60.2 C61.1 C62.2 C63.2 C64.2 C65.2 C66.2 C69.2 C70.2 C71.2 C72.2 C73.2 C74.2 C75.2 C76.2 C78.2 C79.2 C80.1 C81.1 C82.1 C83.2 C84.2 C85.2 C86.2 C87.2 C88.2 C89.2 C90.2 C91.2 C93.2 C94.2 C95.2 C96.1 C97.1 C98.1 C99.2 C100.2 C101.2 C102.2 C103.2 C104.2 C106.2 C108.2 C110.2 C111.2 C112.2 C113.2 C114.2 C119.2 C125.2 C126.1 C127.2 C128.2 D1.1 D3.1(ANODE) D4.2 D5.1(ANODE) D6.1(ANODE) H1.1(A) H2.1(A) H3.1(A) H4.1(A) J1.3 J1.5(S1) J1.6(S2) J2.6(VSS2) J2.10(GND_2) J2.11(GND_1) J2.12(PAD1) J2.13(PAD2) J3.1 J3.4 J3.7 J3.10 J3.13 J3.16 J3.21 J3.23 J3.27 J3.31(S1) J3.32(S2) J4.5(GND1) J4.6(GND2) J4.7(GND3) J4.8(GND4) J4.9(GND5) J4.10(GND6) J4.11(GND7) J5.7 J5.9(S1) J5.10(S2) J6.3(S1) J6.4(S2) J7.3(S1) J7.4(S2) J8.2 J8.5(S1) J8.6(S2) R3.1 R8.1 R9.1 R14.2 R16.2 R17.1 R18.2 R21.1 R26.2 R27.1 R41.2 R46.1 R47.1 R49.1 R50.2 R59.1 R64.2 R71.1 R78.1 R88.1 R89.1 R92.1 R98.1 SW1.1 SW2.1 U1.2(GND) U2.2(GND) U3.2(GND) U4.2(GND) U5.2(GND) U6.C9(DDRPLL_VSSA) U6.G5(PLL_AVSS) U6.G6(VSS1) U6.G7(VSS2) U6.G8(VSS3) U6.G9(VSS4) U6.G10(VSS5) U6.G11(VSS6) U6.G12(VSS7) U6.G13(VSS8) U6.J6(VSS9) U6.J7(VSS10) U6.J8(VSS11) U6.J9(VSS12) U6.J10(VSS13) U6.J11(VSS14) U6.J12(VSS15) U6.K6(VSS16) U6.K7(VSS17) U6.K8(VSS18) U6.K9(VSS19) U6.K10(VSS20) U6.K11(VSS21) U6.K12(VSS22) U6.L6(VSS23) U6.L7(VSS24) U6.L8(VSS25) U6.L9(VSS26) U6.L10(VSS27) U6.L11(VSS28) U6.L12(VSS29) U6.M7(VSS30) U6.M8(VSS31) U6.M9(VSS32) U6.M10(VSS33) U6.M11(VSS34) U6.M12(VSS35) U6.M13(VSS36) U6.N5(CSI_VSSA) U6.N12(VSS37) U6.N13(SADC_AGND) U6.P4(CODEC_AVSS) U7.4(GND) U8.33(GND) U10.7(GND) Y1.2 Y1.4
VBUS: TP10.1 U6.U3(VBUS)
VCC_0V8: C21.1 C22.1 C23.2 C43.1 C44.1 C45.1 C46.1 C47.1 C48.1 C49.1 C50.1 C52.1 C53.1 C55.1 C113.1 FB4.1 FB8.2 L4.2 R63.2 TS1.1 U6.H5(VDD1) U6.H6(VDD2) U6.H7(VDD3) U6.H8(VDD4) U6.H9(VDD5) U6.H10(VDD6) U6.H11(VDD7) U6.H12(VDD8) U6.H13(VDD9) U6.J5(VDD10) U6.J13(VDD11) U6.K5(VDD12) U6.K13(VDD13) U6.L5(VDD14) U6.L15(VDD_RTC) U6.M5(VDD15) U6.M6(VDD16) U6.N6(VDD17) U6.N7(VDD18) U6.N8(VDD19) U6.N9(VDD20) U6.N10(VDD21)
VCC_1V8: C16.1 C17.1 C31.1 C38.1 C76.1 C83.1 C87.1 C88.1 C114.1 FB1.2 FB3.2 FB5.1 FB7.1 FB9.2 L5.2 R20.1 R62.1 R86.2 TP5.1 U6.C4(VDDIO2) U6.K2(VDDIO18_2) U6.L17(VDDIO_RTC) U6.N11(VDDIO18_1) U6.N16(SADC_VREFP) U6.N17(SADC_AVDD)
VCC_3V3: C4.1 C5.1 C39.1 C51.1 C81.2 C89.1 C90.1 C91.1 C92.1 C99.1 C100.1 D2.1(ANODE) FB2.2 FB6.1 J3.30 J8.1 L1.2 Q1.2(SOURCE) R2.2 R22.2 R34.1 R37.1 R44.1 R55.2 R56.2 R57.1 R58.1 R65.2 R68.2 R69.2 R70.2 R87.1 R94.2 TP1.1 U6.J14(VDDIO33_2) U6.P9(VDDIO33_1) U7.8(VCC) U8.14(DVDD33_1)
VCC_5V: C2.1 C10.1 C11.1 C12.1 C13.1 C18.1 C19.1 C20.1 C108.1 J3.28 J3.29 L2.2 R1.1 R5.1 R6.1 R10.1 R11.1 R85.2 TP4.1 U1.4(IN) U3.4(IN) U4.4(IN) U5.4(IN) U10.6(VDD)
VCC_12V: C1.1 C7.1 C8.1 D1.2 J1.4 R4.1 TP2.1 U2.5(VIN)
VCC_DDR: C9.1 C15.1 C24.1 C25.1 C26.1 C27.1 C28.1 C32.1 C33.1 C34.1 C35.1 C37.1 C40.2 C41.1 L3.2 R7.2 R15.2 TP3.1 U6.E6(VDDMEM1) U6.E7(VDDMEM2) U6.E8(VDDMEM3) U6.E9(VDDMEM4) U6.E10(VDDMEM5) U6.E11(VDDMEM6) U6.E12(VDDMEM7) U6.F5(DDRVDD1) U6.F6(DDRVDD2) U6.F7(DDRVDD3) U6.F8(DDRVDD4) U6.F9(DDRVDD5) U6.F10(DDRVDD6) U6.F11(DDRVDD7) U6.F12(DDRVDD8)
VDDMSC0: C93.1 C94.1 J2.4(VDD) Q1.3(DRAIN) R29.1 R30.1 R31.1 R32.1 R33.1
ACTA: J5.6 R74.2 R77.1
BOOTSEL0: R55.1 SW1.2 U6.A9(BOOT_SEL0_PC00)
BOOTSEL1: R56.1 R59.2 U6.B9(BOOT_SEL1_PC01)
CAM_MIPI_RST: J3.18 U6.E3(SA2_PA18)
CIM_MCLK: J3.22 R67.1
CLK_CTL: R92.2 U8.12(RXD[3]/CLK_CTL)
CORE_FB: C23.1 R63.1 R64.1 U5.5(FB)
CSI_VCC08: C84.1 C85.1 FB8.1 U6.N2(CSI_VCCA08)
CSI_VCC18: C29.1 C86.1 FB9.1 U6.K3(CSI_VCCA18)
DDR_VREF: C40.1 C42.2 R15.1 R17.2 U6.E5(DDR_VREF)
DDRPLL: C54.1 C64.1 FB1.1 U6.B8(DDRPLL_VCCA)
EN_DLDO: R27.2 R69.1 U6.U15(EN_DLDO)
EXCLKI: C80.2 R23.2 U6.C1(EXCLK_XIN) Y1.1
EXCLKO: R23.1 R24.2 U6.D2(EXCLK_XOUT)
GMAC_MDCK: U6.R10(GMAC_MDCK_SMB2_SDA_PB10) U8.22(MDC)
GMAC_MDIO: R37.2 U6.T10(GMAC_MDIO_SMB2_SCK_PB11) U8.23(MDIO)
GMAC_PHY_CLK: R66.1 U8.31(XTAL_IN)
GMAC_RST_N: C125.1 R70.1 R99.2 U6.A11(DMIC_CLK_SMB2_SCK_PB28) U8.21(RESET_N)
GMAC_RXD0: U6.U13(GMAC_RXD0_PWM6_PB15) U8.9(RXD[0])
GMAC_RXD1: R44.2 U6.R12(GMAC_RXD1_PWM7_PB16) U8.10(RXD[1])
GMAC_RXDV: U6.U9(GMAC_RXDV_PWM3_PB09) U8.26(CRS/CRS_DV)
GMAC_TXCLK: R19.1 U6.T12(GMAC_TXCLK_PB06)
GMAC_TXD0: U6.R11(GMAC_TXD0_PWM4_PB13) U8.16(TXD[0])
GMAC_TXD1: U6.T11(GMAC_TXD1_PWM5_PB14) U8.17(TXD[1])
GMAC_TXEN: U6.U11(GMAC_TXEN_PWM2_PB08) U8.20(TXEN)
HPOUTL: C107.2 U6.T1(HPOUTL)
I2C0_SCK: J3.20 U6.J4(SD7_SMB0_SCK_PA13)
I2C0_SDA: J3.19 U6.J1(SD6_SMB0_SDA_PA12)
IR: J3.26 U6.B12(DMIC_DAT0_UART4_TXD_PB29)
IRCUTN: J3.25 U6.E17(MSC1_D1_PB18)
IRCUTP: J3.24 U6.E16(MSC1_D0_PB17)
LINKA: J5.8 R75.2 R76.1
MCLK: R67.2 U6.E1(SA1_DVP_MCLK_PA15)
MDI_RN: R40.2 R73.2 U9.1(TD+/RD+)
MDI_RP: R39.2 R72.2 U9.3(TD-/RD-)
MDI_TN: R28.2 R36.2 U9.6(RD+/TD+)
MDI_TP: R13.2 R35.2 U9.8(RD-/TD-)
MICBIAS: C78.1 C79.1 C110.1 R81.1 U6.P3(MICBIAS)
MICNL: C68.2 C105.1 J6.1 R48.1
MICPL: C67.2 C105.2 J6.2 R51.2
MIPI_RX_CLKN: J3.2 U6.M2(CSI_CLKN_DVP_D4)
MIPI_RX_CLKP: J3.3 U6.L3(CSI_CLKP_DVP_D5)
MIPI_RX_DN0: J3.5 U6.L2(CSI_DATAN0_DVP_D0)
MIPI_RX_DN1: J3.8 U6.N1(CSI_DATAN1_DVP_D2)
MIPI_RX_DP0: J3.6 U6.L1(CSI_DATAP0_DVP_D1)
MIPI_RX_DP1: J3.9 U6.M3(CSI_DATAP1_DVP_D3)
MSC0_CLK_PB04: J2.5(CLK) R25.1
MSC0_CMD_PB05: J2.3(CMD) R30.2 U6.G17(MSC0_CMD_PB05)
MSC0_D0_PB00: J2.7(DAT0) R29.2 U6.H16(MSC0_D0_PB00)
MSC0_D1_PB01: J2.8(DAT1) R31.2 U6.J15(MSC0_D1_PB01)
MSC0_D2_PB02: J2.1(DAT2) R32.2 U6.G15(MSC0_D2_PB02)
MSC0_D3_PB03: J2.2(DAT3) R33.2 U6.G16(MSC0_D3_PB03)
PHY_LED0: R74.1 U6.R13(LED0)
PHY_LED1: R75.1 U6.R15(LED1)
PHY_RST_N: C61.2 R99.1 U6.T13(PHY_RST)
PHYLED0: R77.2 R88.2 U8.24(LED0/PHYAD[0])
PHYLED1: R76.2 R89.2 U8.25(LED1/PHYAD[1])
PLL_AVDD: C30.1 C63.1 FB3.1 U6.D3(PLL_AVDD)
POR_CTRL: R20.2 R78.2 U6.K16(POR_CTL)
PPRST_: C111.1 R62.2 SW2.2 U6.L16(PPRST_)
RD_N: R73.1 U6.U17(RD_N)
RD_P: R72.1 U6.T17(RD_P)
RST_OUT: TP8.1 U6.J16(RST_OUT)
RX+: J5.3 U9.14(TX-/RX-)
RX-: J5.4 U9.16(TX+/RX+)
RX_DV: R68.1 U6.P14(RX_DV)
RXD3: R65.1 R71.2 U6.R14(RXD3)
RXDV: R87.2 U8.8(RXDV)
SD0_CD_N: C92.2 J2.9(CD) Q1.1(GATE) R34.2 U6.B11(DRV_VBUS_SMB2_SDA_PB27)
SFC_CS_N: R22.1 U6.T4(SFC0_CE_PA28) U7.1(C\S\)
SFC_SCLK: U6.R6(SFC0_CLK_PA27) U7.6(SCLK)
SFC_SIO0: U6.U5(SFC0_DT_IO0_PA23) U7.5(SI/SIO0)
SFC_SIO1: U6.R5(SFC0_DR_IO1_PA24) U7.2(SO/SIO1)
SFC_SIO2: U6.T5(SFC0_WP_IO2_PA26) U7.3(W\P\/SIO2)
SFC_SIO3: U6.T6(SFC0_HOLD_IO3_PA25) U7.7(R\E\S\E\T\/SIO3)
SPEAK_EN: R50.1 U6.B10(GPIO_PB31) U10.1(/SD)
TD_N: R28.1 U6.U16(TD_N)
TD_P: R13.1 U6.T16(TD_P)
TRXN0: R36.1 U8.4(TRXN0)
TRXN1: R40.1 U8.6(TRXN1)
TRXP0: R35.1 U8.3(TRXP0)
TRXP1: R39.1 U8.5(TRXP1)
TX+: J5.1 U9.9(RX-/TX-)
TX-: J5.2 U9.11(RX+/TX+)
UART1_RX: R61.2 U6.F16(UART1_RXD_PB24)
UART1_RXD: J8.3 R57.2 R61.1
UART1_TX: R60.2 U6.F15(UART1_TXD_PB23)
UART1_TXD: J8.4 R58.2 R60.1
USB0PN: D5.2(CATHODE) J4.2(D-) R100.2
USB0PP: D3.2(CATHODE) J4.3(D+) R101.2
USB_AVD08: C71.1 C72.1 FB4.2 U6.R4(USB_AVD08)
USB_AVD18: C36.1 C73.1 FB5.2 U6.T3(USB_AVD18)
USB_AVD33: C74.1 C75.1 FB6.2 U6.R3(USB_AVD33)
USBID: TP7.1 U6.U2(USB0ID)
N16515966: C10.2 R6.2 R8.2 U2.3(FB)
N16516036: R4.2 U2.4(EN)
N16516040: C6.1 U2.1(BS)
N16516056: C6.2 L2.1 U2.6(LX)
N16516370: C3.1 R1.2 U1.1(EN)
N16516568: C4.2 R2.1 R3.2 U1.5(FB)
N16516600: L1.1 U1.3(LX)
N16516732: D2.2(CATHODE) R14.1
N16516898: C14.1 R5.2 U3.1(EN)
N16517024: C9.2 R7.1 R9.2 U3.5(FB)
N16517036: L3.1 U3.3(LX)
N16520392: C95.1 C119.1 D6.2(CATHODE) J4.1(VBUS) R85.1
N16524050: J7.2 U10.5(VO+)
N16524058: J7.1 U10.8(VO-)
N16524110: R53.1 U10.4(-IN)
N16524120: C107.1 R53.2
N16524124: C106.1 R52.2
N16524196: R52.1 U10.3(+IN)
N16524342: C56.2 R51.1 R81.2
N16524476: C56.1 R48.2 R49.2
N16557488: C82.2 R24.1 Y1.3
N16609473: R16.1 U6.F13(DDR_ZQ)
N16609477: R18.1 U6.D9(RZQ)
N16629326: R46.2 U8.28(RXER)
N16629374: R47.2 U8.32(XTAL_OUT)
N16629796: R41.1 U8.1(PBIAS)
N16629982: C103.1 C104.1 U8.29(DVDDL_REG)
N16630018: C101.1 C102.1 U8.2(AVDDL_REG)
N16630046: R94.1 U8.30(NC)
N16630124: C98.2 U9.7(CT2)
N16630144: D4.1 R93.2 U9.10(CT3) U9.13(MCT) U9.15(CT4)
N16630182: C97.2 U9.5(CT)
N16630194: C96.2 U9.2(CT1)
N16630328: C126.2 R93.1
N16642093: C112.1 R10.2 U5.1(EN)
N16642355: L4.1 U5.3(LX)
N16679971: R21.2 U6.D4(EFUSE_AVDD)
N16680187: C65.1 C66.1 FB7.2 U6.R1(CODEC_AVDD)
N16680357: C69.1 C70.1 U6.R2(VCM)
N16685513: R66.2 U6.T9(GMAC_PHY_CLK_PB07)
N16707574: R101.1 U6.T2(USB0PP)
N16707578: R100.1 U6.U1(USB0PN)
N16707590: C68.1 U6.P2(MICNL)
N16707598: TP9.1 U6.P15(SADC_VIN0)
N16710875: R25.2 U6.H15(MSC0_CLK_PB04)
N16712105: C67.1 U6.N3(MICPL)
N16792128: R26.1 U6.T15(RBIAS)
N16932770: C62.1 R11.2 U4.1(EN)
N16932828: L5.1 U4.3(LX)
N16932830: C16.2 R86.1 R98.2 U4.5(FB)
N16990134: R19.2 U8.15(TXC)

Pads without a net: J1 1 2; J3 11 12 14 15 17; J4 4; J5 5; U6 A1 A2 A3 A5 A7 A13 A15 A16 A17 B1 B2 B3 B4 B5 B6 B7 B13 B14 B15 B16 B17 C2 C3 C5 C6 C7 C8 C10 C11 C12 C13 C14 C15 C16 C17 D14 D15 D16 E2 E15 F2 F3 G1 G2 G3 H2 H3 J2 J3 J17 K15 L13 M15 M16 N15 P16 R7 R8 R9 R17 T7 T8 U7; U8 11 13 18 19 27; U9 4 12; U10 2

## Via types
v1: diameter 0.406, hole 0.203, TOP to BOTTOM, 501 vias

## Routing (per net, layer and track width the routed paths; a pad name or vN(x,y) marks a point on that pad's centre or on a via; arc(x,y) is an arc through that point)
AVDD33: length 3.8
  TOP w0.254: U8.7 v1(17.58,14.78)
  BOTTOM w0.254: FB2.1 18.92,15.86 C127.1 18.4,15.77 C128.1 17.58,15.74 v1(17.58,14.78)
AVDDL_REG: length 2.1
  TOP w0.254: U6.R16 v1(27.48,19.29)
  BOTTOM w0.305: C60.1 C59.1 27.52,19.25 v1(27.48,19.29)
DVDD1V2OUT: length 2.9
  TOP w0.254: v1(25.7,20.9) 25.9,20.9 25.91,20.91 U6.T14
  BOTTOM w0.305: C57.1 C58.1 25.71,20.89 v1(25.7,20.9)
GND: length 244.3
  TOP w0.102: U6.J12 U6.K12 v1(30.72,22.53)
  TOP w0.127: U6.G8 v1(33.32,24.48) U6.G9 ; U6.G11 v1(33.32,23.18) U6.G10 ; U6.K10 v1(30.72,23.18) ; U6.G5 v1(33.32,27.08) ; U6.K11 v1(30.72,22.53) ; U6.L11 v1(30.07,22.53) ; U6.M11 v1(29.42,22.53) ; U6.N13 v1(28.77,21.23) ; U6.G13 v1(33.32,21.88) U6.G12 ; U6.G7 v1(33.32,25.78) U6.G6 ; U6.L12 v1(30.07,21.88) ; U6.M12 v1(29.42,21.88)
  TOP w0.203: 15.87,33 v1(15.83,33) 15.53,33 15.39,33.15 15.39,34.54 ; v1(22.84,32.85) 22.18,32.85 21.22,33.82 C110.2 20.9,33.99 20.62,34.26 v1(20.62,34.42) 20.31,34.11 16.97,34.11 v1(16.86,34) 15.71,34 v1(14.8,34.9) 13.05,34.9 12.65,34.49 v1(12.65,32.69) 12.85,32.69 14.08,31.46 C108.2 14.33,31.52 v1(14.68,31.52) 15.57,31.52 16.1,30.99 v1(16.79,30.99) 16.79,30.61 17.06,30.33 19.71,30.33 20.02,30.65 v1(20.02,30.77) R49.1 ; v1(26.81,24.5) 25.86,25.45 23.39,25.45 22.35,24.41 v1(21.59,24.41) v1(20.9,24.41) v1(20.27,24.41) 16.79,24.41 15.44,25.76 v1(15.41,25.76) ; J2.10 22.37,14.27 23.47,15.37 25.09,15.37 27.58,17.86 27.58,17.98 v1(28.23,18.64) ; v1(34.25,34.58) 33.85,34.58 33.6,34.33 33.6,33.16 33.89,32.87 C82.1 35,32.87 Y1.4 ; v1(24.97,29.75) v1(22.11,29.75) 19.89,27.53 15.36,27.53 14.19,26.37 13.03,26.37 v1(12.72,26.06) 12.39,25.73 12.39,25.15 12.67,24.87 v1(14.02,24.87) 14.17,24.87 15.06,25.76 v1(15.41,25.76) ; v1(18.9,22.41) 18.67,22.64 C125.2 ; R92.1 21.56,17.68 21.61,17.63 v1(21.66,17.63) ; SW2.1 41.09,25.5 v1(40.76,25.83) ; v1(15.41,25.76) 15.41,26.11 15.87,26.57 20.52,26.57 v1(20.62,26.47) 21.51,26.47 23.14,28.09 v1(23.14,28.37) ; R21.1 38.82,28.35 v1(38.82,28.35) ; R26.2 24.32,18.26 24.52,18.06 v1(24.91,18.06) 23.8,16.94 22.83,16.94 21.54,15.65 19.73,15.65 v1(19.25,15.16) ; 20.65,31.14 20.94,30.85 22.73,30.85 22.83,30.75 v1(24.95,30.75)
  TOP w0.254: U6.N12 29.06,22.21 v1(28.72,21.87) ; v1(30.07,21.88) U6.M13 ; U6.P4 v1(28.14,27.71) ; U6.C9 v1(35.92,24.48) ; U6.M8 U6.L8 ; v1(37.79,30.76) 37.79,31.32 38.63,32.16 38.63,33.17 38.24,33.57 C80.1 37.26,34.35 Y1.2 v1(36.92,34.99) 36.6,35.31 v1(36.04,35.31) 34.97,35.31 v1(34.25,34.58) ; v1(22.07,19.13) 21.45,19.75 C99.2 21.26,19.72 C100.2
  TOP w0.305: v1(10.61,14.05) R41.2 R47.1 ; v1(31.37,24.48) 31.37,24.48 U6.K9 ; v1(31.37,24.48) 31.37,24.48 U6.J8 ; v1(31.37,24.48) 31.7,24.16 U6.J9 ; v1(31.37,24.48) 31.05,24.81 U6.K8 v1(30.72,25.13) ; v1(30.72,25.13) U6.L7 U6.M7 ; v1(30.72,25.13) U6.K7 ; v1(30.72,25.13) U6.L8 ; R49.1 20.65,31.14 ; R46.1 C104.2 ; C104.2 10.71,17.7 ; C104.2 11.24,16.79 C103.2 10.78,17.14 v1(10.61,17.14) ; v1(30.72,23.83) U6.L9 30.4,24.15 v1(30.07,23.83) ; v1(30.72,23.83) U6.L10 ; v1(30.72,23.83) U6.K9 ; U6.K7 v1(31.37,25.78) ; U6.K7 v1(30.72,25.78) U6.L6 ; R88.1 14.8,22.73 v1(15.13,23.06) ; U6.J6 31.69,26.11 v1(31.37,25.78) ; v1(30.07,23.83) 29.75,24.16 U6.M9 ; v1(30.07,23.83) 29.75,23.51 U6.M10 ; U6.J7 v1(31.37,25.78) ; v1(31.37,25.78) U6.K6 ; R59.1 v1(39.21,25.17) ; U6.J11 v1(31.37,23.18) U6.J10 ; C61.1 24.46,19.86 v1(24.51,19.81) ; R78.1 v1(31.19,16.69) ; U6.N5 v1(28.77,27.08) ; U10.7 v1(12.34,28.66) 12.57,28.66 14.08,30.16 C108.2 ; v1(30.72,24.48) U6.K9 ; U6.N12 v1(29.42,22.53) ; C106.2 v1(20.15,28.4) ; R89.1 v1(13.92,23.09) ; v1(39.29,24.03) 39.16,23.9 R18.2 ; R50.2 v1(18.89,28.07)
  TOP w0.406: v1(27.1,15.34) 27.1,15.32 27.12,15.32 J2.6
  TOP w0.508: 9.84,26.11 J4.8 ; J4.8 10.82,26.96 ; J4.8 8.86,26.96 ; 9.84,21.26 J4.9 ; J4.9 8.86,22.11 ; J4.9 10.82,22.11 ; J4.9 9.84,22.97
  L2_GND w0.508: 9.84,21.26 J4.9 ; J4.9 9.84,22.97 ; J4.9 8.86,22.11 ; J4.9 10.82,22.11 ; 9.84,26.11 J4.8 ; J4.8 8.86,26.96 ; J4.8 9.84,27.82 ; J4.8 10.82,26.96
  L3_PWR w0.508: J4.9 10.82,22.11 ; J4.9 9.84,22.97 ; J4.9 9.84,21.26 ; J4.9 8.86,22.11 ; 8.86,26.96 J4.8 ; J4.8 9.84,27.82 ; J4.8 10.82,26.96 ; J4.8 9.84,26.11
  BOTTOM w0.203: C86.2 33.59,29.59 v1(33.8,29.59) 33.95,29.59 C30.2 ; R71.1 21.68,17.7 21.68,17.64 v1(21.66,17.63) 21.66,17.58 21.68,17.56 21.68,17.49 22.06,17.11 R27.1 ; v1(10.61,14.05) 10.5,13.94 J8.2 ; v1(15.41,25.76) 16.35,24.82 19.25,24.82 20.11,25.68 20.11,26.34 18.89,27.56 v1(18.89,28.07) 18.89,28.88 v1(16.79,30.99) 14.6,33.17 ; 20.02,18.38 C112.2
  BOTTOM w0.254: C17.2 25.35,8.33 v1(25.65,8.03) ; C11.2 33.85,7.01 v1(33.52,7.34) ; 31.57,9.81 v1(31.57,9.47) v1(31.57,7.44) v1(31.57,6.55) 31.57,5.69 v1(31.62,5.64) ; R8.1 31.57,9.8 ; C70.2 25.37,29.36 v1(24.97,29.75) ; C88.2 v1(37.14,26.05) ; C12.2 v1(32.84,7.21)
  BOTTOM w0.305: J4.5 10.51,25.84 v1(10.74,25.6) ; v1(38.82,28.35) 38.43,27.97 C42.1 ; C24.2 36.24,23.18 v1(35.92,23.18) ; C24.2 36.79,22.63 C25.2 36.89,21.92 C33.2 ; C24.2 C26.2 ; C64.2 39.01,24.92 39.21,25.12 v1(39.21,25.17) ; C15.2 34.9,17.51 34.89,17.53 v1(34.84,17.53) ; v1(27.75,12.4) 27.21,11.86 24.38,11.86 23.9,11.38 v1(23.9,10.85) v1(23.9,9.47) v1(23.9,8) v1(23.9,6.27) 23.9,5.28 24.2,4.98 R98.1 v1(24.44,4.37) ; U2.2 v1(35.2,8.79) ; R9.1 v1(33.8,13.97) ; v1(20.62,26.47) 20.62,26.4 21.01,26.01 22.14,26.01 22.55,26.42 C36.2 C73.2 ; C69.2 C70.2 ; U1.2 v1(21.15,7.11) ; C41.2 v1(37.79,30.76) ; v1(19.3,8.03) 19.3,8.32 C5.2 ; v1(35.92,24.48) 36.41,24.97 C27.2 ; R17.1 v1(38.88,28.85) ; C76.2 C38.2 v1(27.81,17.04) ; C18.2 26.74,3.3 v1(26.31,2.87) ; v1(37.14,26.05) 37.01,26.19 C28.2 ; v1(27.47,24.48) 27.38,24.39 C39.2 C89.2 26.49,24.17 v1(26.81,24.5) ; C62.2 v1(29.59,8.26) ; v1(40.13,11.38) 39.82,11.07 C7.2 C8.2 ; C54.2 v1(39.29,24.03) ; C43.2 27.51,27.11 v1(27.47,27.08) 26.97,27.08 26.57,26.68 C72.2 C71.2 ; v1(21.18,21.09) 21.12,21.03 U5.2 ; C59.2 C60.2 ; D3.1 v1(12.01,26.07) ; U4.2 v1(27.5,7.14) ; C3.2 v1(23.24,8.26)
  BOTTOM w0.406: C98.1 v1(11.25,8.94) ; C97.1 v1(14.93,7.32) ; C14.2 v1(39.52,17.37) ; C96.1 v1(16.33,7.14) ; v1(15.13,23.06) 15.13,22.45 C19.2 15.32,22 C20.2
  BOTTOM w0.508: J4.9 10.82,22.11 ; J4.9 9.84,21.26 ; J4.9 8.86,22.11 ; 9.84,26.11 J4.8 ; J4.8 9.84,27.82 ; J4.8 8.86,26.96 ; J4.8 10.82,26.96
  vias: v1(5.71,34.54) v1(5.71,31.27) v1(5.74,22.1) v1(5.66,19.13) v1(5.71,16.18) v1(5.69,13.92) v1(5.69,12.37) v1(5.71,10.16) v1(5.74,8.89) v1(5.71,7.59) v1(5.71,5.89) v1(5.69,3.86) v1(5.76,29.36) v1(5.79,27.1) v1(5.81,24.54) v1(6.7,15.47) v1(6.93,6.55) v1(7.59,29.41) v1(7.77,31.14) v1(7.92,17.27) v1(7.95,6.91) v1(8.3,33.71) v1(8.28,25.93) v1(8.28,24.51) v1(8.33,23.24) v1(8.4,26.95) v1(8.45,30.43) v1(8.45,22.15) v1(8.66,37.29) v1(8.91,3.91) v1(8.89,0.66) v1(9.34,34.82) v1(9.29,10.97) v1(9.5,3.07) v1(9.6,1.93) v1(10.16,30.63) v1(10.16,8.64) v1(10.31,10.64) v1(10.44,0.66) v1(10.51,34.82) v1(10.61,4.27) v1(11.01,27.42) v1(11.02,26.34) v1(11.02,24.87) v1(10.99,7.87) v1(11.22,12.09) v1(11.63,13.36) v1(11.76,37.26) v1(11.78,35.56) v1(12.04,34.32) v1(12.11,26.92) v1(12.21,30.61) v1(12.19,9.07) v1(12.52,22.56) v1(12.67,36.5) v1(13.18,28.47) v1(13.18,23.8) v1(13.33,37.29) v1(13.69,30.61) v1(13.71,9.17) v1(13.7,5.25) v1(13.86,8.18) v1(14.02,6.25) v1(14.12,36.5) v1(14.27,29.29) v1(14.3,10.74) v1(14.98,5.31) v1(15.06,19.2) v1(15.06,17.93) v1(15.06,16.66) v1(15.2,37.31) v1(15.29,35.62) v1(15.41,11.73) v1(15.52,30.63) v1(15.97,12.5) v1(16.13,6.32) v1(16.21,26.48) v1(16.33,19.2) v1(16.33,17.93) v1(16.33,16.66) v1(16.58,9.47) v1(16.84,12.37) v1(16.79,5.61) v1(16.86,10.87) v1(17.01,4.29) v1(17.4,35.05) v1(17.37,9.45) v1(17.52,8.15) v1(17.47,5.71) v1(17.6,19.2) v1(17.62,17.93) v1(17.6,16.66) v1(17.9,11.63) v1(18.06,4.22) v1(18.46,14.3) v1(18.55,20.43) v1(18.64,8.03) v1(18.64,7.42) v1(18.74,37.36) v1(18.69,15.16) v1(18.87,4.24) v1(19.3,7.42) v1(19.6,4.01) v1(19.95,6.31) v1(19.96,3.12) v1(20.29,34.72) v1(20.6,11.89) v1(20.82,9.09) v1(20.82,0.64) v1(21.08,3.91) v1(21.05,2.82) v1(21.22,6.11) v1(21.36,9.09) v1(21.65,21.08) v1(21.83,35.74) v1(21.87,12.24) v1(23.24,30.76) v1(23.41,11.96) v1(23.36,0.64) v1(23.49,35.26) v1(24,3.48) v1(24.51,2.82) v1(24.56,24.56) v1(24.96,8.03) v1(24.96,7.42) v1(25.36,35.92) v1(25.6,4.22) v1(25.65,7.42) v1(25.88,32.37) v1(25.9,0.64) v1(26.03,17.7) v1(26.33,6.25) v1(26.31,3.81) v1(27.15,9.07) v1(27.36,35.7) v1(27.43,3.91) v1(27.4,2.82) v1(27.57,6.13) v1(27.68,9.07) v1(28.34,36.07) v1(28.34,30.86) v1(28.27,0.64) v1(28.86,16.46) v1(29,27.58) v1(29.13,37.36) v1(29.14,32.18) v1(29.05,12.17) v1(29.94,10.97) v1(30.39,30.95) v1(30.63,0.64) v1(31.01,37.36) v1(31.09,35.97) v1(31.11,29.74) v1(32.81,10.95) v1(32.89,37.34) v1(33.32,27.64) v1(33.41,32.54) v1(33.4,2.13) v1(33.45,0.66) v1(33.69,9.01) v1(33.69,8.57) v1(33.8,15.32) v1(33.8,14.68) v1(33.8,13.34) v1(33.96,27.69) v1(34.34,10.36) v1(34.4,32.35) v1(34.46,37.34) v1(34.62,27.73) v1(34.57,7.14) v1(34.57,6.47) v1(34.84,16.74) v1(34.97,36.42) v1(35.26,27.08) v1(35.33,10.97) v1(35.27,6.78) v1(35.28,3.1) v1(35.53,9.75) v1(35.81,17.78) v1(35.86,16.31) v1(36.24,36.4) v1(36.16,7.8) v1(36.29,0.66) v1(36.42,37.34) v1(37.11,17.27) v1(37.23,14.3) v1(37.18,3.07) v1(37.28,15.14) v1(37.41,21.41) v1(37.51,20.7) v1(37.64,36.3) v1(37.77,16.1) v1(37.89,37.31) v1(38.02,34.14) v1(38.12,2.11) v1(38.53,35.41) v1(38.84,30.4) v1(38.81,15.16) v1(39.16,37.34) v1(39.19,22.58) v1(39.16,5.97) v1(39.21,4.11) v1(39.27,29.51) v1(39.26,0.69) v1(39.62,20.9) v1(39.75,32.41) v1(39.98,17.83) v1(39.95,5.26) v1(40.13,12.12) v1(40.29,15.33) v1(40.43,10.13) v1(40.89,10.95) v1(41.02,33.55) v1(41.15,21.05) v1(41.15,18.9) v1(41.54,32.77) v1(41.96,12.57) v1(42.06,10.95) v1(42.31,34.24) v1(42.3,32.95) v1(42.34,31.34) v1(42.34,28.93) v1(42.34,26.59) v1(42.26,13.41) v1(42.34,3.84) v1(42.37,24.1) v1(42.37,21.61) v1(42.36,18.97) v1(42.37,16.02)
VBUS: length 1.4
  TOP w0.254: U6.U3 25.56,28.06 TP10.1
VCC_0V8: length 19.1
  TOP w0.203: U6.N6 v1(28.77,26.43) ; U6.M5 v1(29.42,27.08) ; U6.H5 v1(32.67,27.08) ; U6.H9 v1(32.67,24.48) U6.H8 ; U6.L5 v1(30.07,27.08) ; U6.H11 v1(32.67,23.18) U6.H10 ; U6.H7 v1(32.67,25.78) U6.H6 ; U6.H12 v1(32.67,21.88) ; v1(32.02,27.08) U6.J5
  TOP w0.254: U6.N6 U6.M6 U6.M5 ; U6.N7 28.37,25.46 v1(28.37,25.45) ; U6.K5 v1(31.37,27.08) ; U6.N9 29.1,24.15 v1(28.77,23.83) 29.09,23.51 U6.N10 ; U6.K13 v1(31.37,21.23) ; U6.L15 30.4,20.77 v1(30.78,21.16) ; U6.N8 28.51,24.81 v1(28.37,24.66) ; U6.H13 v1(32.02,21.88) U6.J13
  BOTTOM w0.102: C113.1 30.45,20.83 v1(30.78,21.16)
  BOTTOM w0.254: FB4.1 24.33,26.09
  BOTTOM w0.305: C22.1 22.31,25.16 21.99,25.48 ; 21.99,25.48 20.57,25.48 19.19,24.09 C23.2 R63.2 ; 21.99,25.48 22.65,25.48
  vias: v1(30.07,21.23)
VCC_1V8: length 87.8
  TOP w0.203: R62.1 38.73,16.92 38.21,17.44 ; R20.1 v1(30.3,16.46)
  TOP w0.254: U6.K2 31.24,28.9 v1(31.24,29.16) ; v1(35.92,27.08) U6.C4 ; U6.L17 v1(30.11,18.67) ; v1(29.26,18.39) 29.1,18.55 U6.N17 U6.N16 ; U6.N11 v1(28.34,22.86)
  TOP w0.635: v1(24.91,10.29) v1(25.7,10.29) 33.21,10.29 35.25,12.33 35.25,14.48 40.31,19.53 40.31,21.98 v1(39.82,22.46) v1(39.82,23.11)
  L3_PWR w0.254: 27.86,20.62 28.14,20.91 ; 28.14,20.91 28.14,22.65 v1(28.34,22.86) ; 28.14,20.91 28.42,20.62
  L3_PWR w0.305: v1(20.77,29.13) 20.77,27.66 26.78,21.65 26.78,21.02 27.17,20.62 28.42,20.62 28.87,20.18 28.87,18.78 v1(29.26,18.39)
  BOTTOM w0.254: v1(28.34,22.86) 28.34,22.59 C114.1 C31.1 ; 39.56,27.09 39.82,26.82 ; 39.56,27.09 39.82,27.35 ; 39.56,27.09 C88.1 35.93,27.09 v1(35.92,27.08) ; FB7.1 20.65,29.26 v1(20.77,29.13) 20.77,27.23 21.35,26.65 FB5.1 ; v1(39.82,23.11) 39.8,23.14 FB1.2 ; FB9.2 33.39,30.46 32.97,30.89 31.78,30.89 31.53,30.63 C87.1 31.54,30.39 31.54,29.46 v1(31.24,29.16) ; 29.42,17.86 C76.1 ; v1(30.11,18.67) 30.16,18.62 C83.1 30.3,17.79 v1(30.3,16.46)
  BOTTOM w0.305: C17.1 24.93,9.71 24.44,9.23 C16.1 R86.2
  BOTTOM w0.406: FB9.2 33.55,30.25 34.06,30.76 FB3.2 34.19,31.12 35.07,32 38.07,32 39.82,30.25 v1(39.82,23.11) v1(39.82,22.46) ; v1(30.3,16.46) v1(29.64,16.46) 29.42,16.68 C38.1 29.42,17.86 ; C76.1 29.42,18.23 v1(29.26,18.39)
VCC_3V3: length 113.9
  TOP w0.203: v1(10.54,16.46) 10.54,15.99 10.76,15.77 R94.2 ; R55.2 38.82,26.72 v1(38.82,26.54) R56.2 ; R37.1 15.78,22.71 v1(16.33,22.71) ; R70.2 v1(21.37,11.98) ; v1(27.61,16.43) 28.23,16.43 28.52,16.72 R68.2
  TOP w0.254: C99.1 20.76,18.66 v1(20.72,18.69) 20.71,18.68 C100.1 U8.14 ; v1(33.09,20.83) 33.04,20.78 31.85,20.78 31.8,20.83 31.77,20.83 U6.J14 ; v1(21.18,16.38) 21.29,16.5 R44.1 ; U6.P9 v1(28.12,23.83)
  L3_PWR w0.203: v1(16.52,13.37) 16.52,15.63 16.53,15.65
  L3_PWR w0.254: 33.64,20.28 33.93,19.99 ; 33.64,20.28 v1(33.09,20.83) ; 33.64,20.28 33.64,19.77 33.52,19.66 ; 33.64,20.28 34.22,20.28 34.36,20.42 ; 19.1,16.38 18.36,15.65 14.8,15.65 14.27,16.18 10.82,16.18 v1(10.54,16.46) ; v1(25.14,24.41) 25.14,24.89 22.33,27.7 22.33,28.7 v1(21.31,29.72)
  L3_PWR w0.406: v1(21.18,16.38) 19.1,16.38 18.79,16.69 18.79,18.92 16.33,21.39 v1(16.33,22.71)
  BOTTOM w0.203: R58.1 10.88,16.8 v1(10.54,16.46) ; J8.1 11.59,12.75 R57.1 ; U7.8 11.02,28.93 9.18,28.93 R22.2 ; 20.21,13.13 v1(21.37,11.98) ; R87.1 v1(16.52,13.37)
  BOTTOM w0.254: v1(20.72,18.69) 21.18,18.24 v1(21.18,16.38) 21.15,16.41 FB2.2 ; v1(28.12,23.83) 28.12,23.45 27.8,23.13 C39.1 C89.1 25.15,23.13 25.14,23.14 v1(25.14,24.41) ; v1(10.54,16.46) 9.27,16.46 8.96,16.15 8.96,13.11 9.32,12.75 J8.1 10.5,11.73 9.79,11.01 D2.1 ; U7.8 15.07,24.88 C81.2 15.7,24.5 15.83,24.5 16.33,24 v1(16.33,22.71) ; v1(33.09,20.83) 33.16,20.77 C51.1 C90.1 ; v1(21.31,29.72) 21.62,29.4 FB6.1
  BOTTOM w0.305: 18.09,9.32 18.49,9.71 C5.1 ; 18.09,9.32 18.09,9.94 ; 18.09,9.32 C4.1 R2.2 ; 25.14,23.14 25.14,19.09 R65.2 R69.2 24.14,16.36 C92.1
  BOTTOM w0.406: v1(21.18,16.38) 21.23,16.33
  BOTTOM w0.635: v1(27.61,16.43) v1(27.07,16.43) 26.99,16.52 Q1.2 24.88,16.04 C92.1 R34.1 C91.1 21.52,16.04 21.23,16.33 ; v1(40.53,29.26) v1(40.53,29.84) 40.53,30.61 37.77,33.38 30.77,33.38 J3.30
VCC_5V: length 67.7
  TOP w0.305: U10.6 12.09,29.31 12.99,30.21 v1(12.99,30.43) C108.1
  L3_PWR w0.305: v1(12.99,30.43) 11.54,28.98 11.54,21.25 9.5,19.2 7.92,19.2 v1(7.46,18.75)
  L3_PWR w0.406: 32.65,33.68 32.65,36.36 32.23,36.78 v1(30.25,36.78) ; 32.65,33.68 32.65,33.3 ; 32.65,33.68 33.03,33.3 ; 32.65,33.3 33.03,33.3 ; 32.65,33.3 32.65,32.92 ; 33.03,33.3 40.2,33.3 41.8,31.7 41.8,15.8 v1(38.48,12.47) ; 33.03,33.3 32.65,32.92 ; 32.65,32.92 v1(32.65,32.45)
  BOTTOM w0.254: U5.4 17.63,20.08 18.35,19.37 R10.1
  BOTTOM w0.305: R6.1 C10.1 32.06,5.98 32.44,5.6 C12.1
  BOTTOM w0.406: J3.28 29.25,33.31 30.11,32.45 v1(32.65,32.45) ; J3.29 29.94,36.78 v1(30.25,36.78)
  vias: v1(6.7,19.56) v1(6.68,18.75) v1(7.49,19.53) v1(22.37,2.13) v1(22.4,1.35) v1(23.19,2.13) v1(23.19,1.35)
VCC_12V: length 3
  BOTTOM w0.254: R4.1 36.13,9.05 36.39,8.79 U2.5
  vias: v1(39.47,6.81) v1(40.08,8.2) v1(40.08,7.42) v1(40.69,6.81) v1(41.14,7.8) v1(42.06,7.8)
VCC_DDR: length 22.7
  TOP w0.127: U6.E12 v1(34.62,21.88) ; U6.E8 v1(34.62,24.48) U6.E9 ; U6.E10 v1(34.62,23.18) U6.E11 ; U6.F6 v1(33.97,25.78) U6.F7 ; U6.F9 v1(33.97,24.48) ; U6.E7 v1(34.62,25.78) U6.E6 ; U6.F5 v1(33.97,27.08) ; U6.F10 v1(33.97,23.18) U6.F11 ; U6.F12 v1(33.97,21.88)
  L3_PWR w0.254: v1(34.62,25.78) 35.89,25.78 38.3,28.19 v1(38.3,30.07)
  BOTTOM w0.254: v1(38.3,30.07) 38.3,30.96 37.87,31.39 36.57,31.39 36.38,31.2 C41.1 R15.2 36.39,29.86 C40.2
  BOTTOM w0.305: C15.1 34.78,18.6 34.35,18.17 C9.1 R7.2
VDDMSC0: length 15.6
  TOP w0.305: J2.4 v1(29.32,12.85)
  BOTTOM w0.203: R32.1 R33.1 R30.1 29.65,13.61 C94.1
  BOTTOM w0.254: R29.1 27.14,12.87 27.15,12.85 ; R31.1 23.81,13.25 24.71,12.34 26.64,12.34 27.15,12.85 ; 27.15,12.85 v1(29.32,12.85)
  BOTTOM w0.305: Q1.3 28.85,15.57 29.29,15.13 C93.1 C94.1 29.29,12.88 v1(29.32,12.85)
ACTA: length 3.6
  TOP w0.102: R77.1 R74.2 10.51,18.73 10.51,18.26 10.22,17.97 J5.6
BOOTSEL0: length 20.7
  TOP w0.102: U6.A9 37.11,24.16 37.51,24.56 39.37,24.56 39.77,24.97 39.77,26.63 R55.1 41.53,28.39 41.53,31.52 37.08,35.97 SW1.2
BOOTSEL1: length 2.8
  TOP w0.102: U6.B9 36.63,24.54 37.14,24.54 R59.2 R56.1
CAM_MIPI_RST: length 13.8
  TOP w0.102: v1(32.61,31.34) 32.61,30.2 33.98,28.83 33.98,28.37 U6.E3
  BOTTOM w0.102: J3.18 24.25,33.18 24.58,32.84 27.56,32.84 29.05,31.34 v1(32.61,31.34)
CIM_MCLK: length 9
  TOP w0.102: R67.1 33.31,31.28 v1(33.24,31.34)
  BOTTOM w0.102: J3.22 26.25,33.28 26.46,33.07 27.68,33.07 29,31.75 32.84,31.75 v1(33.24,31.34)
CLK_CTL: length 1.5
  TOP w0.102: U8.12 20.25,17.68 R92.2
CORE_FB: length 2.9
  BOTTOM w0.305: C23.1 R63.1 R64.1 17.24,23.03 U5.5
CSI_VCC08: length 3.1
  TOP w0.178: U6.N2 29.1,28.86 28.7,29.26
  TOP w0.203: v1(28.8,29.74) 28.7,29.64 28.7,29.26
  BOTTOM w0.203: C85.1 C84.1 FB8.1
  BOTTOM w0.254: C85.1 28.77,29.72 v1(28.8,29.74)
CSI_VCC18: length 3.2
  TOP w0.254: v1(31.37,28.37) 31.05,28.06 U6.K3
  BOTTOM w0.254: v1(31.37,28.37) 32.22,28.37 C29.1 C86.1 32.32,30.22 FB9.1
DDR_VREF: length 5.4
  TOP w0.254: U6.E5 v1(34.62,27.08)
  BOTTOM w0.254: v1(34.62,27.08) 35.1,27.56 36,27.56 C40.1 37.26,27.95 C42.2 R17.2 37.27,29.72 R15.1
DDRPLL: length 3.3
  TOP w0.254: U6.B8 36.43,24.99 v1(36.95,24.99)
  BOTTOM w0.254: FB1.1 37.65,23.17 C54.1 C64.1 37.58,24.99 v1(36.95,24.99)
EN_DLDO: length 5.5
  TOP w0.102: v1(23.11,17.4) 23.57,17.86 23.57,18.72 24.02,19.18 25.09,19.18 26.17,20.26 U6.U15
  BOTTOM w0.102: v1(23.11,17.4) 23.1,17.39 R27.2
EXCLKI: length 5.1
  TOP w0.102: U6.C1 35.6,29.82 R23.2 36.6,30.38 36.92,30.7 Y1.1 36.94,32.53 C80.2
EXCLKO: length 2.6
  TOP w0.102: R24.2 R23.1 35.11,28.87 U6.D2
GMAC_MDCK: length 14.1
  TOP w0.102: U8.22 15.58,20.64 17.14,22.2 17.14,22.89 17.29,23.04 26.14,23.04 26.3,23.19 27.48,23.19 U6.R10
GMAC_MDIO: length 13.9
  TOP w0.102: U6.T10 27.08,23.44 26.15,23.44 25.98,23.27 17.19,23.27 16.91,22.99 16.91,22.57 15.95,21.6 R37.2 15.08,20.96 U8.23
GMAC_PHY_CLK: length 16.1
  TOP w0.102: v1(15.74,23.34) 15.9,23.5 23.12,23.5 R66.1 ; U8.31 v1(13.25,16.68)
  L3_PWR w0.102: v1(13.25,16.68) 13.94,17.37 13.94,19.46 15.55,21.07 15.55,23.15 v1(15.74,23.34)
GMAC_RST_N: length 45.5
  TOP w0.102: v1(18.49,21.95) 18.07,21.95 C125.1 16.9,21.6 16.08,20.78 U8.21 ; R99.2 23.57,19.56 v1(23.11,19.1) ; v1(23.44,11.35) 32.76,11.35 34.44,13.03 34.44,15.42 36.7,17.68 37.31,17.68 39.21,19.58 39.21,22 38.35,22.86 U6.A11
  TOP w0.203: R70.1 v1(23.44,11.35)
  L3_PWR w0.102: 22.12,18.31 22.12,18.19 ; 22.12,18.31 18.67,21.77 18.56,21.77 18.49,21.84 v1(18.49,21.95) ; 22.12,18.31 22.25,18.31 ; 22.12,18.19 22.25,18.31 ; 22.12,18.19 22.12,12.68 v1(23.44,11.35) ; v1(23.11,19.1) 22.32,18.31 22.25,18.31
GMAC_RXD0: length 12.5
  TOP w0.102: U6.U13 26.41,21.64 23.16,21.64 22.68,21.16 22.68,17.2 21.43,15.95 20.75,15.95 20.52,16.18 U8.9
GMAC_RXD1: length 13.3
  TOP w0.102: U8.10 20.15,16.68 R44.2 20.69,17.22 21.81,17.22 22.45,17.86 22.45,21.31 23.01,21.87 27.46,21.87 U6.R12
GMAC_RXDV: length 18.4
  TOP w0.102: U6.U9 26.34,24 24.94,24 24.76,24.18 23.03,24.18 22.63,23.77 15.25,23.77 15.12,23.65 13.89,23.65 13.38,23.14 13.38,20.6 13.05,20.27 13.05,19.56 13.43,19.18 U8.26
GMAC_TXCLK: length 5.8
  TOP w0.102: R19.1 22.48,21.74 22.83,22.1 27.04,22.1 U6.T12
